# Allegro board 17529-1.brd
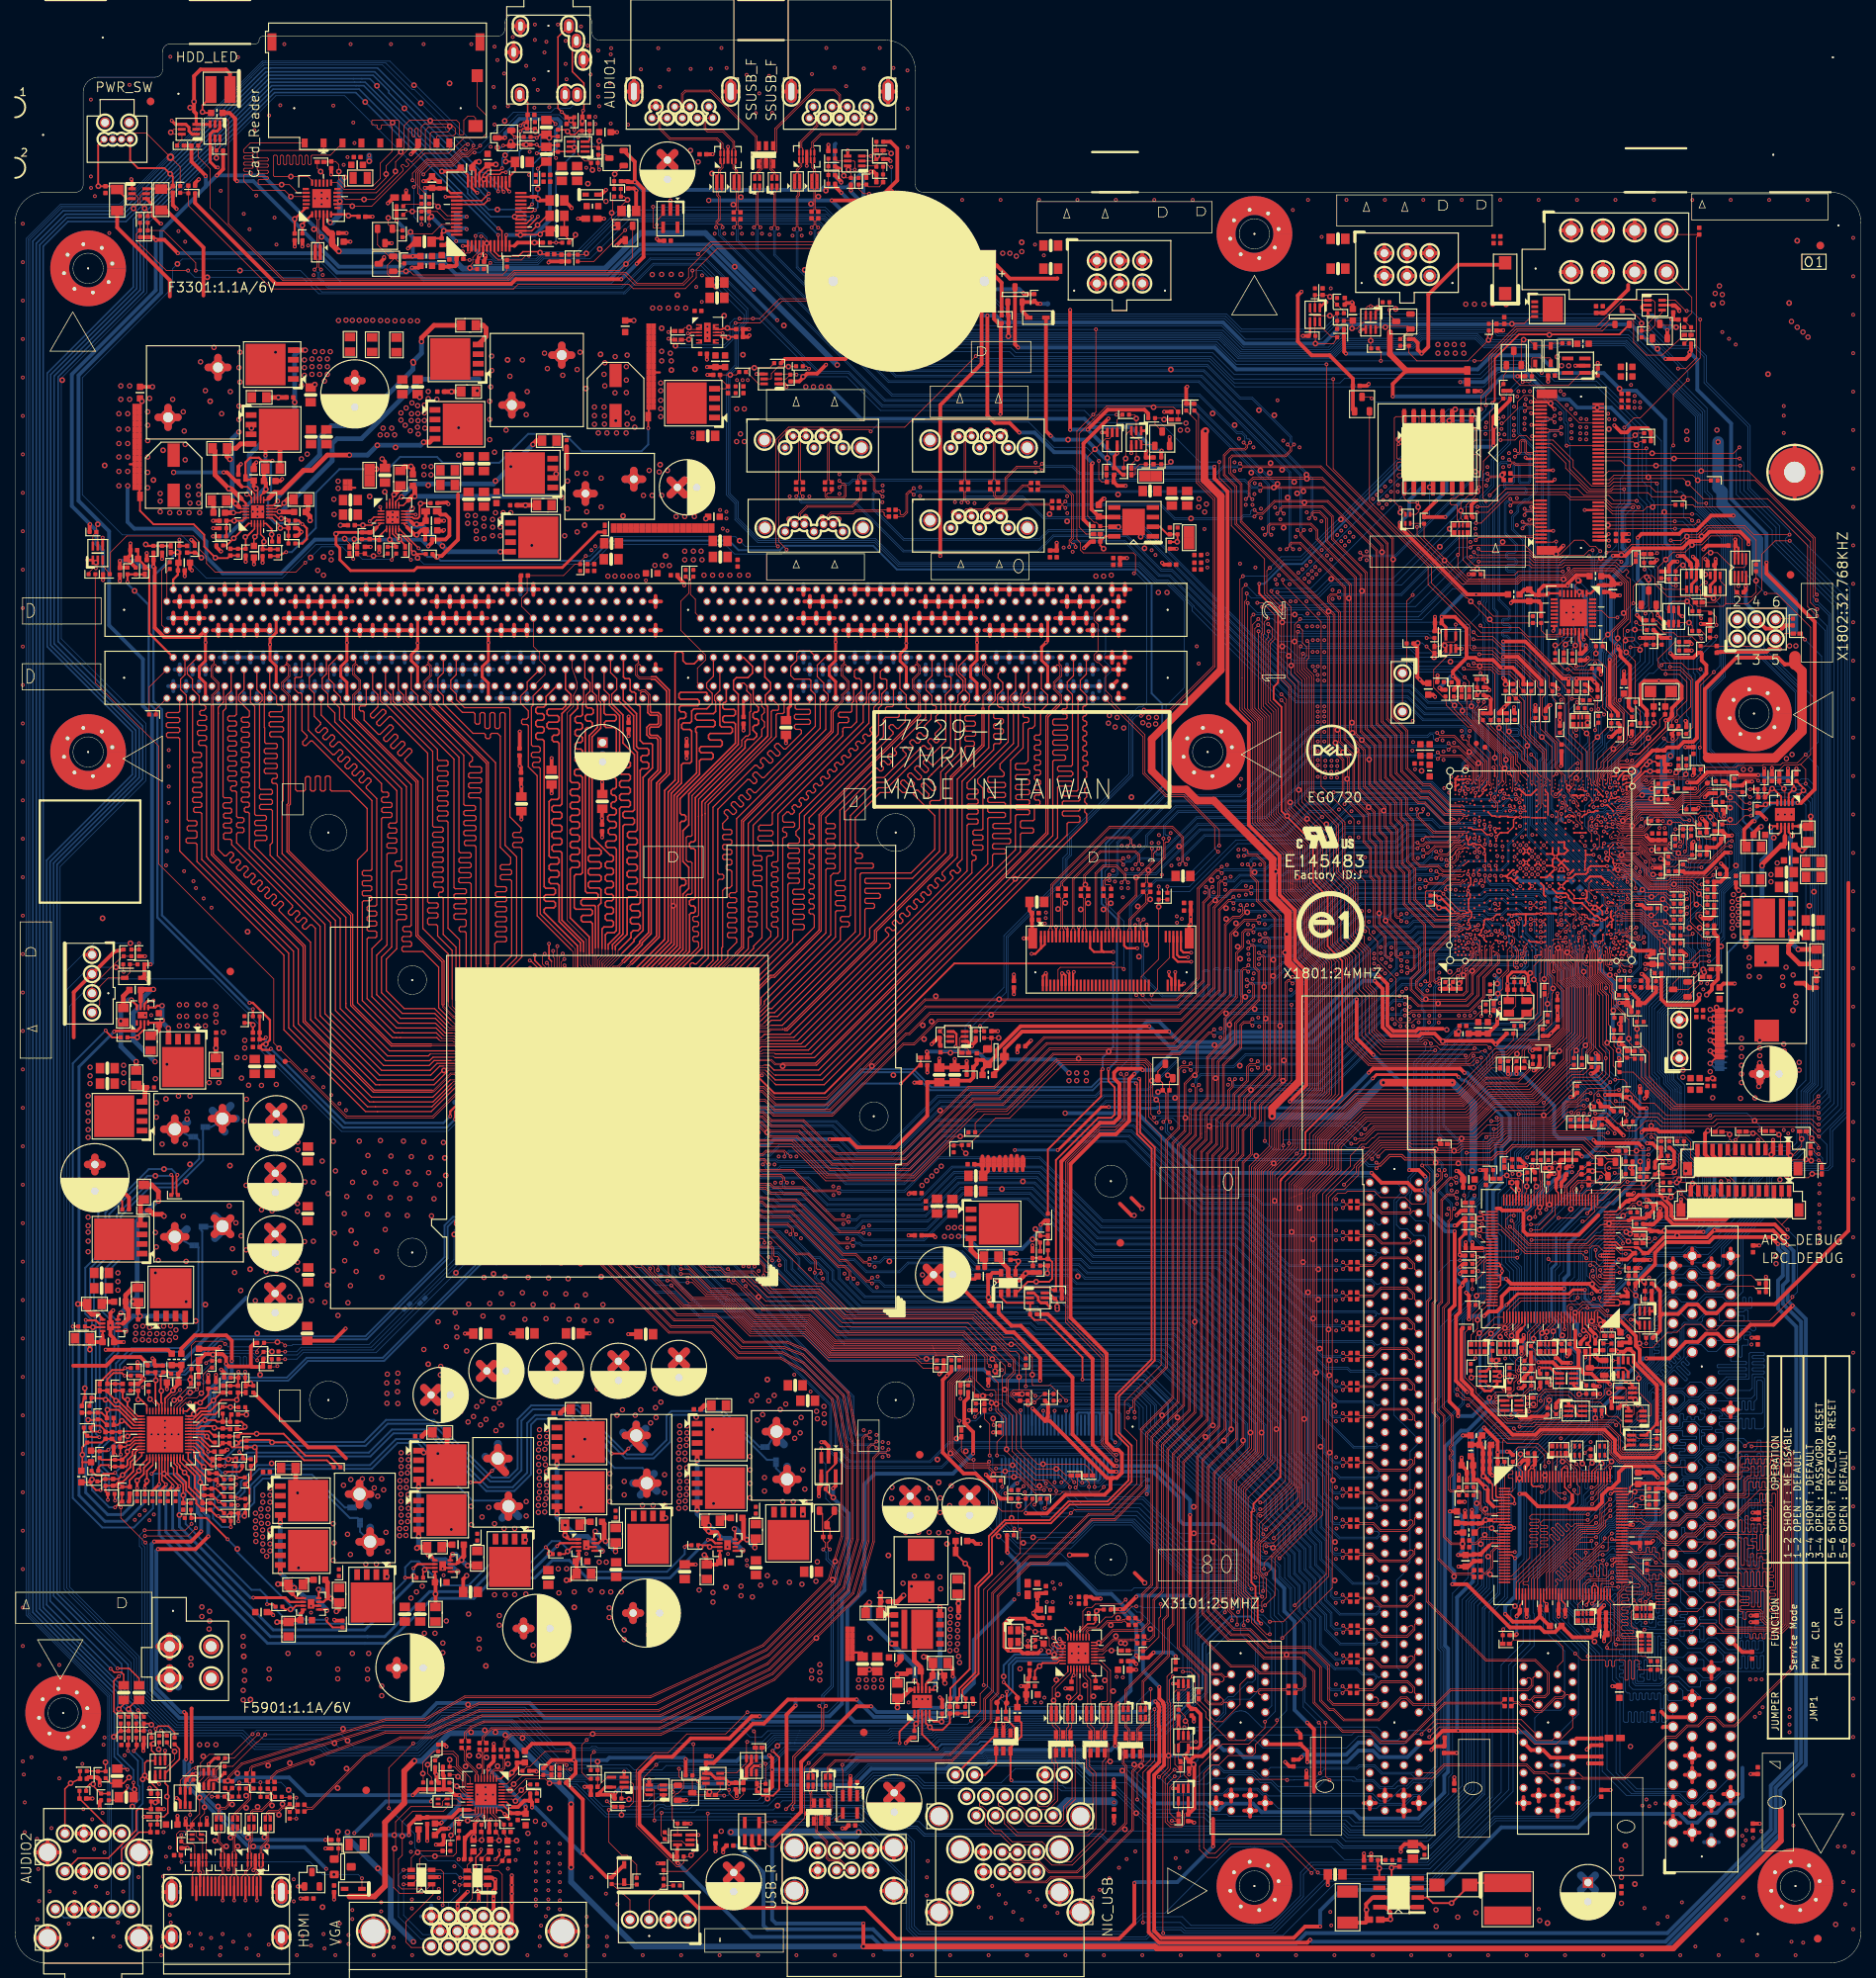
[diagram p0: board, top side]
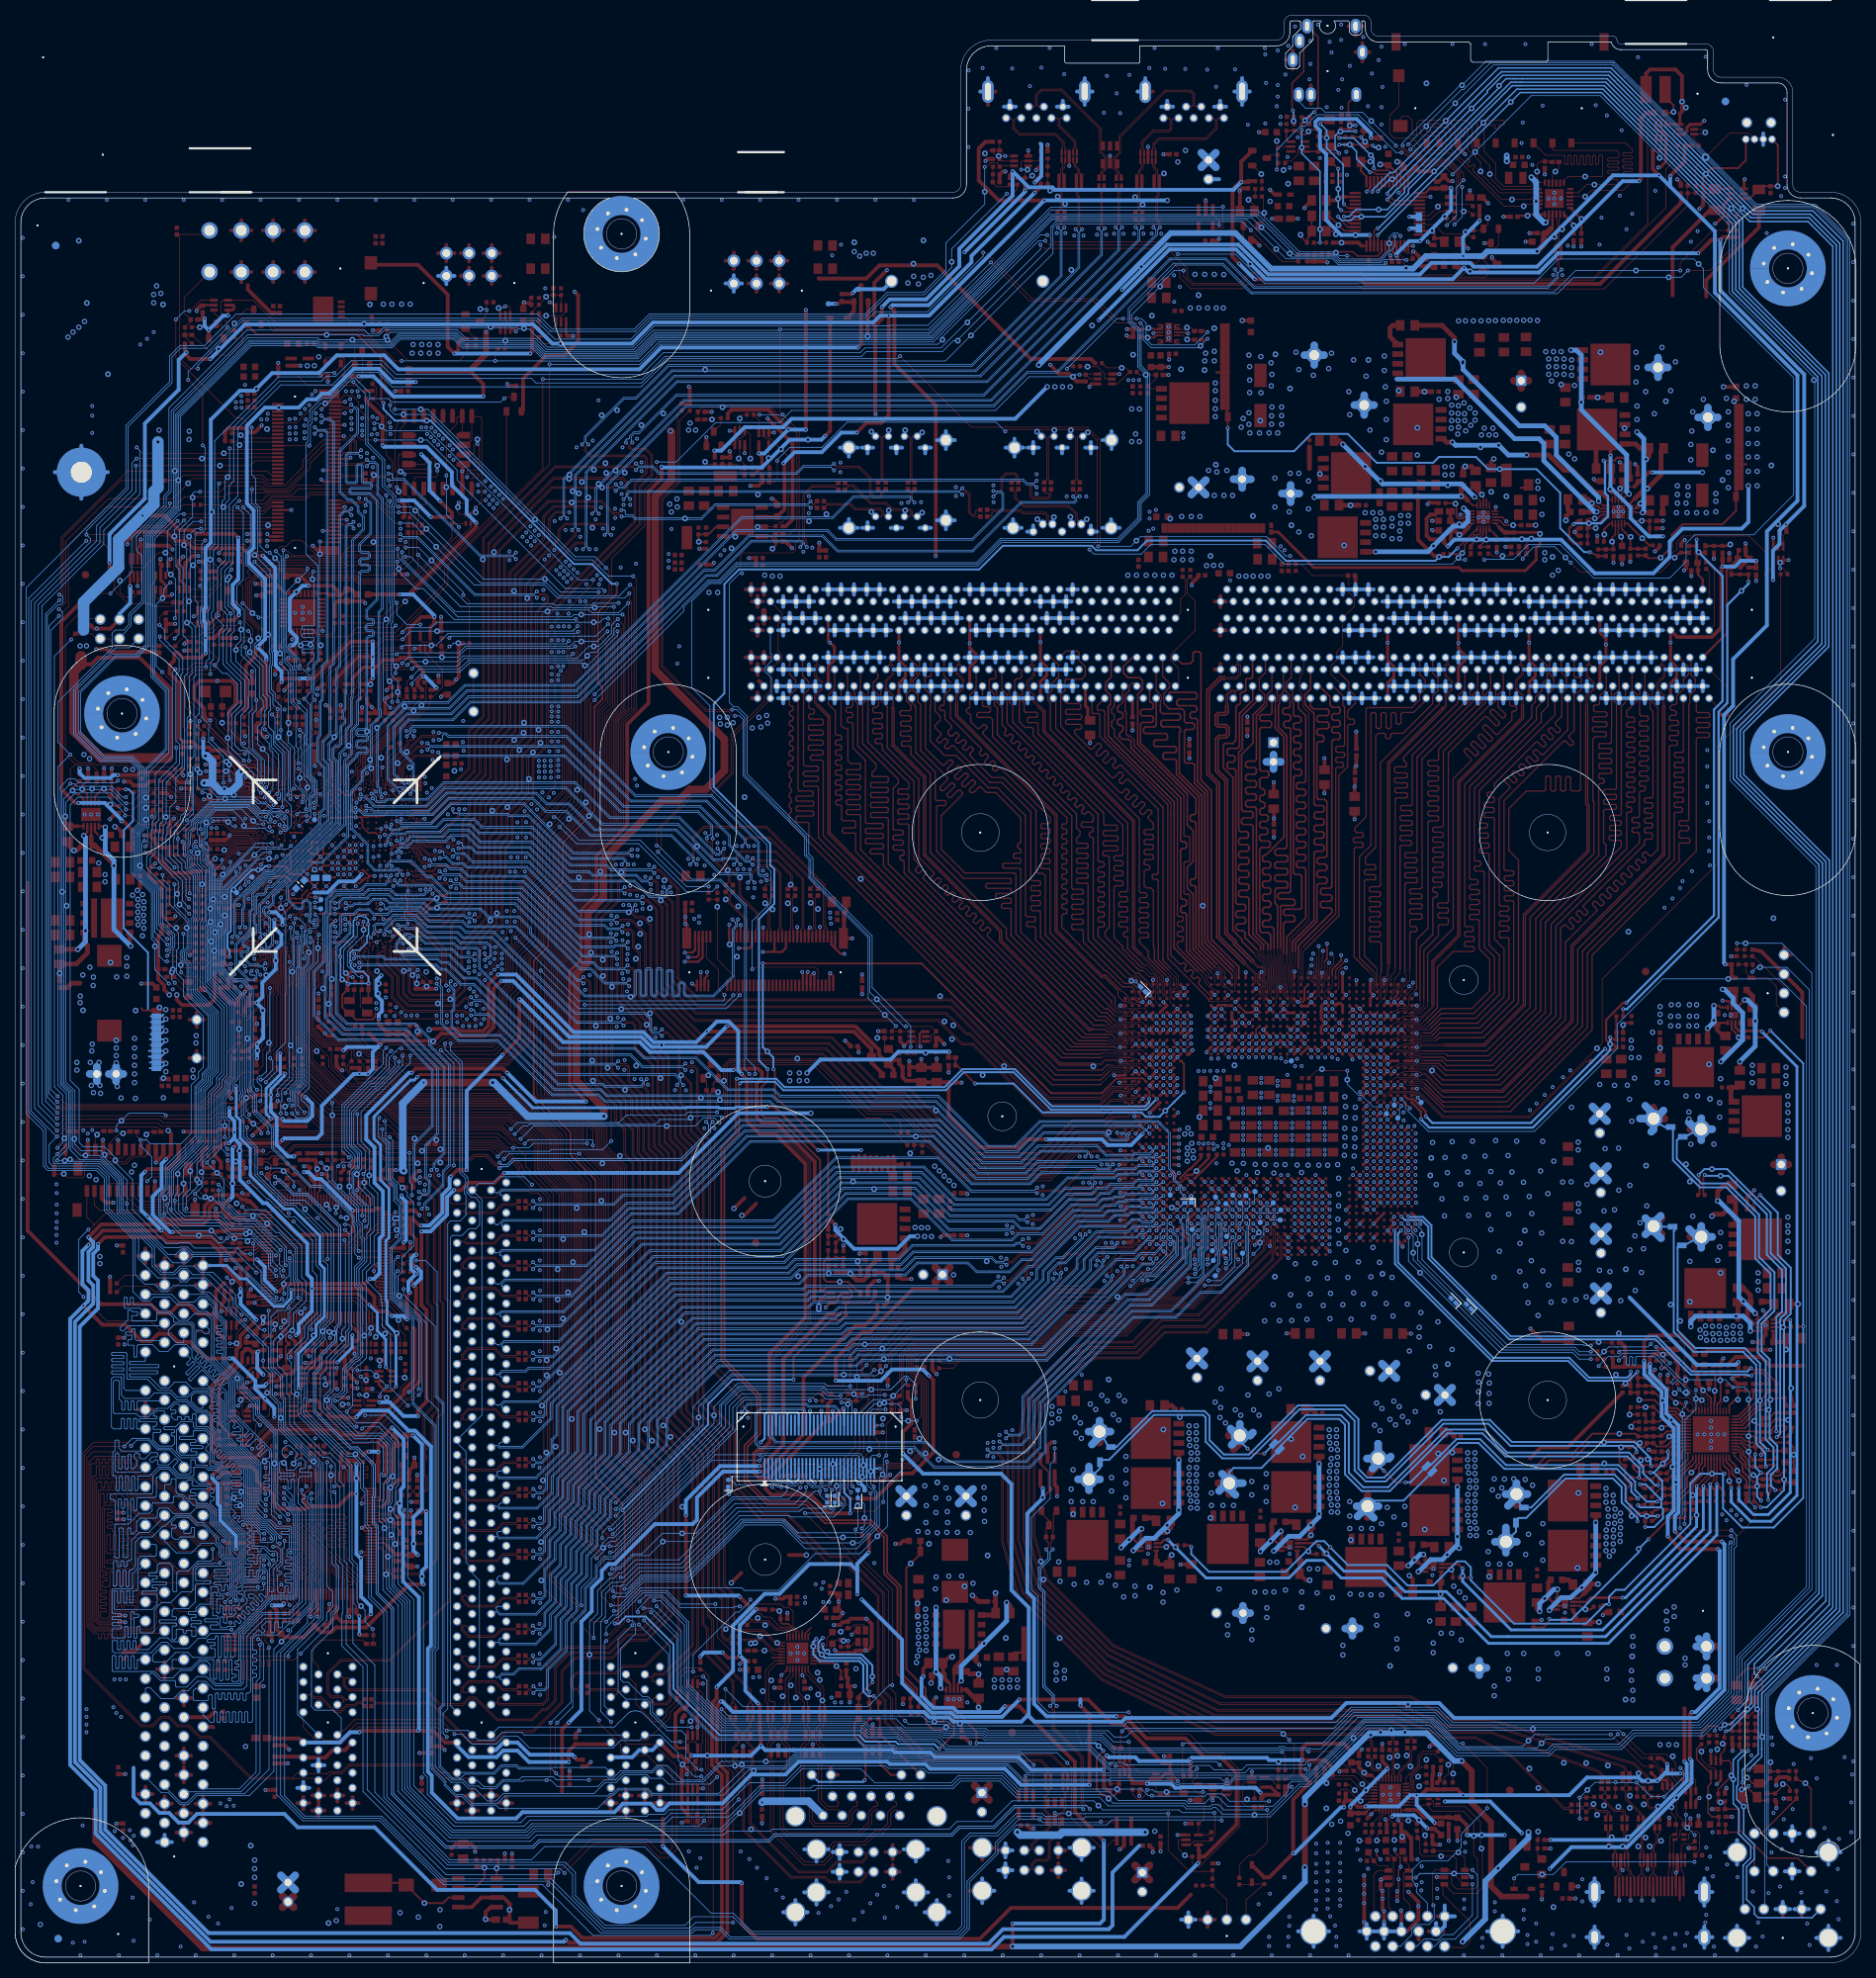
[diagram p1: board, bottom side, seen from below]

Outline 244 x 257.4 mm; copper layers: TOP, L2VCC, L3, BOTTOM. Coordinates in mm from the lower left corner of the outline.
Outline path: 0,230 0,4 arc(1.17,1.17) 4,0 240,0 arc(242.83,1.17) 244,4 244,230 arc(242.83,232.83) 240,234 120,234 arc(119.29,234.29) 119,235 119,250.1 arc(117.83,252.93) 115,254.1 77.25,254.1 arc(76.54,254.39) 76.25,255.1 76.25,256.4 arc(75.96,257.11) 75.25,257.4 65.75,257.4 arc(65.04,257.11) 64.75,256.4 64.75,255.6 arc(64.46,254.89) 63.75,254.6 32.75,254.6 arc(32.4,254.45) 32.25,254.1 arc(32.1,253.75) 31.75,253.6 20.5,253.6 arc(19.79,253.31) 19.5,252.6 19.5,250.2 arc(19.21,249.49) 18.5,249.2 11,249.2 arc(9.59,248.61) 9,247.2 9,235 arc(8.71,234.29) 8,234 4,234 arc(1.17,232.83) 0,230 ; 4.35,33.02 arc(6.35,35.02) 8.35,33.02 arc(6.35,31.02) 4.35,33.02 ; 7.65,223.94 arc(9.65,225.94) 11.65,223.94 arc(9.65,221.94) 7.65,223.94 ; 7.65,160.02 arc(9.65,162.02) 11.65,160.02 arc(9.65,158.02) 7.65,160.02 ; 38.91,74.38 arc(41.41,76.88) 43.91,74.38 arc(41.41,71.88) 38.91,74.38 ; 39.01,149.38 arc(41.41,151.78) 43.81,149.38 arc(41.41,146.98) 39.01,149.38 ; 50.59,129.88 arc(52.49,131.78) 54.39,129.88 arc(52.49,127.98) 50.59,129.88 ; 50.59,93.88 arc(52.49,95.78) 54.39,93.88 arc(52.49,91.98) 50.59,93.88 ; 111.61,111.88 arc(113.51,113.78) 115.41,111.88 arc(113.51,109.98) 111.61,111.88 ; 113.91,149.38 arc(116.41,151.88) 118.91,149.38 arc(116.41,146.88) 113.91,149.38 ; 114.01,74.38 arc(116.41,76.78) 118.81,74.38 arc(116.41,71.98) 114.01,74.38 ; 144.86,105.4 arc(146.96,103.3) 144.86,101.2 arc(142.76,103.3) 144.86,105.4 ; 144.86,55.4 arc(146.96,53.3) 144.86,51.2 arc(142.76,53.3) 144.86,55.4 ; 155.65,160.02 arc(157.65,162.02) 159.65,160.02 arc(157.65,158.02) 155.65,160.02 ; 161.83,228.49 arc(163.83,230.49) 165.83,228.49 arc(163.83,226.49) 161.83,228.49 ; 161.83,10.16 arc(163.83,12.16) 165.83,10.16 arc(163.83,8.16) 161.83,10.16 ; 227.87,165.1 arc(229.87,167.1) 231.87,165.1 arc(229.87,163.1) 227.87,165.1 ; 233.35,10.16 arc(235.35,12.16) 237.35,10.16 arc(235.35,8.16) 233.35,10.16 ; 235.25,198.35 arc(236.6,197) 235.25,195.65 arc(233.9,197) 235.25,198.35

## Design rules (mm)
constraint set DEFAULT: min track width 0.127, pair gap 0.102
net group AUD_AZACPU_SDI: nets AUD_AZACPU_SDI AUD_AZACPU_SDI_R
net group AUDIO_HDA_4_5: nets AUD_LINK_SDO_C AUD_LINK_SDO_R1
net group AUDIO_VREFO_20_10: nets LINE2_VREFO MIC2_VREFO
net group CEC_STRAP: nets GPIO_LAN_RESET_N GPIO_PCI_RESET_N
net group DDI_VGA_DATA_CPU_N2: nets DDI_VGA_DATA_C_N2 DDI_VGA_DATA_CPU_N2
net group DDI_VGA_DATA_CPU_N3: nets DDI_VGA_DATA_C_N3 DDI_VGA_DATA_CPU_N3
net group DDI_VGA_DATA_CPU_P2: nets DDI_VGA_DATA_C_P2 DDI_VGA_DATA_CPU_P2
net group DDI_VGA_DATA_CPU_P3: nets DDI_VGA_DATA_C_P3 DDI_VGA_DATA_CPU_P3
net group DDR_MISC: nets M_A_ALERT# M_B_ALERT#
net group DISPLAY_DDC: nets HDMI_CLK_CPU HDMI_DATA_CPU
net group DP_AUX_CON_N: nets DP_AUX_CON_N DP_AUX_CPU_N
net group DP_AUX_CON_P: nets DP_AUX_CON_P DP_AUX_CPU_P
net group HDMI_DATA_CMC_N0: nets HDMI_DATA_CMC_N0 HDMI_DATA_CPU_N0
net group HDMI_DATA_CMC_N1: nets HDMI_DATA_CMC_N1 HDMI_DATA_CPU_N1
net group HDMI_DATA_CMC_N2: nets HDMI_DATA_CMC_N2 HDMI_DATA_CPU_N2
net group HDMI_DATA_CMC_N3: nets HDMI_DATA_CMC_N3 HDMI_DATA_CPU_N3
net group HDMI_DATA_CMC_P0: nets HDMI_DATA_CMC_P0 HDMI_DATA_CPU_P0
net group HDMI_DATA_CMC_P1: nets HDMI_DATA_CMC_P1 HDMI_DATA_CPU_P1
net group HDMI_DATA_CMC_P2: nets HDMI_DATA_CMC_P2 HDMI_DATA_CPU_P2
net group HDMI_DATA_CMC_P3: nets HDMI_DATA_CMC_P3 HDMI_DATA_CPU_P3
net group LAN_MDI0_DN: nets LAN_MDI0_DN LAN_MDI0_DN_C
net group LAN_MDI0_DP: nets LAN_MDI0_DP LAN_MDI0_DP_C
net group LAN_MDI1_DN: nets LAN_MDI1_DN LAN_MDI1_DN_C
net group LAN_MDI1_DP: nets LAN_MDI1_DP LAN_MDI1_DP_C
net group LAN_MDI2_DN: nets LAN_MDI2_DN LAN_MDI2_DN_C
net group LAN_MDI2_DP: nets LAN_MDI2_DP LAN_MDI2_DP_C
net group LAN_MDI3_DN: nets LAN_MDI3_DN LAN_MDI3_DN_C
net group LAN_MDI3_DP: nets LAN_MDI3_DP LAN_MDI3_DP_C
net group LED_4_5: nets SIO_GREEN SIO_YELLOW
net group PCH_LPSS_GSP: nets LPSS_GSPI0_MOSI LPSS_GSPI1_MOSI
net group PCI_CLK: nets PCI_CLK1 PCICLK0
net group PCIE_RX_CON_N5: nets PCIE_RX_CON_N5 PCIE_RX_PCH_N5
net group PCIE_RX_CON_N6: nets PCIE_RX_CON_N6 PCIE_RX_PCH_N6
net group PCIE_RX_CON_P5: nets PCIE_RX_CON_P5 PCIE_RX_PCH_P5
net group PCIE_RX_CON_P6: nets PCIE_RX_CON_P6 PCIE_RX_PCH_P6
net group PCIE_TX_CON_N5: nets PCIE_TX_CON_N5 PCIE_TX_PCH_N5
net group PCIE_TX_CON_N6: nets PCIE_TX_CON_N6 PCIE_TX_PCH_N6
net group PCIE_TX_CON_N7: nets PCIE_TX_CON_N7 PCIE_TX_PCH_N7
net group PCIE_TX_CON_N9: nets PCIE_TX_CON_N9 PCIE_TX_PCH_N9
net group PCIE_TX_CON_N21: nets PCIE_TX_CON_N21 PCIE_TX_PCH_N21
net group PCIE_TX_CON_N22: nets PCIE_TX_CON_N22 PCIE_TX_PCH_N22
net group PCIE_TX_CON_N23: nets PCIE_TX_CON_N23 PCIE_TX_PCH_N23
net group PCIE_TX_CON_N24: nets PCIE_TX_CON_N24 PCIE_TX_PCH_N24
net group PCIE_TX_CON_P5: nets PCIE_TX_CON_P5 PCIE_TX_PCH_P5
net group PCIE_TX_CON_P6: nets PCIE_TX_CON_P6 PCIE_TX_PCH_P6
net group PCIE_TX_CON_P7: nets PCIE_TX_CON_P7 PCIE_TX_PCH_P7
net group PCIE_TX_CON_P9: nets PCIE_TX_CON_P9 PCIE_TX_PCH_P9
net group PCIE_TX_CON_P21: nets PCIE_TX_CON_P21 PCIE_TX_PCH_P21
net group PCIE_TX_CON_P22: nets PCIE_TX_CON_P22 PCIE_TX_PCH_P22
net group PCIE_TX_CON_P23: nets PCIE_TX_CON_P23 PCIE_TX_PCH_P23
net group PCIE_TX_CON_P24: nets PCIE_TX_CON_P24 PCIE_TX_PCH_P24
net group PEG_TX_CON_N0: nets PEG_TX_CON_N0 PEG_TX_CPU_N0
net group PEG_TX_CON_N1: nets PEG_TX_CON_N1 PEG_TX_CPU_N1
net group PEG_TX_CON_N2: nets PEG_TX_CON_N2 PEG_TX_CPU_N2
net group PEG_TX_CON_N3: nets PEG_TX_CON_N3 PEG_TX_CPU_N3
net group PEG_TX_CON_N4: nets PEG_TX_CON_N4 PEG_TX_CPU_N4
net group PEG_TX_CON_N5: nets PEG_TX_CON_N5 PEG_TX_CPU_N5
net group PEG_TX_CON_N6: nets PEG_TX_CON_N6 PEG_TX_CPU_N6
net group PEG_TX_CON_N7: nets PEG_TX_CON_N7 PEG_TX_CPU_N7
net group PEG_TX_CON_N8: nets PEG_TX_CON_N8 PEG_TX_CPU_N8
net group PEG_TX_CON_N9: nets PEG_TX_CON_N9 PEG_TX_CPU_N9
net group PEG_TX_CON_N10: nets PEG_TX_CON_N10 PEG_TX_CPU_N10
net group PEG_TX_CON_N11: nets PEG_TX_CON_N11 PEG_TX_CPU_N11
net group PEG_TX_CON_N13: nets PEG_TX_CON_N13 PEG_TX_CPU_N13
net group PEG_TX_CON_N14: nets PEG_TX_CON_N14 PEG_TX_CPU_N14
net group PEG_TX_CON_N15: nets PEG_TX_CON_N15 PEG_TX_CPU_N15
net group PEG_TX_CON_P0: nets PEG_TX_CON_P0 PEG_TX_CPU_P0
net group PEG_TX_CON_P1: nets PEG_TX_CON_P1 PEG_TX_CPU_P1
net group PEG_TX_CON_P2: nets PEG_TX_CON_P2 PEG_TX_CPU_P2
net group PEG_TX_CON_P3: nets PEG_TX_CON_P3 PEG_TX_CPU_P3
net group PEG_TX_CON_P4: nets PEG_TX_CON_P4 PEG_TX_CPU_P4
net group PEG_TX_CON_P5: nets PEG_TX_CON_P5 PEG_TX_CPU_P5
net group PEG_TX_CON_P6: nets PEG_TX_CON_P6 PEG_TX_CPU_P6
net group PEG_TX_CON_P7: nets PEG_TX_CON_P7 PEG_TX_CPU_P7
net group PEG_TX_CON_P8: nets PEG_TX_CON_P8 PEG_TX_CPU_P8
net group PEG_TX_CON_P9: nets PEG_TX_CON_P9 PEG_TX_CPU_P9
net group PEG_TX_CON_P10: nets PEG_TX_CON_P10 PEG_TX_CPU_P10
net group PEG_TX_CON_P11: nets PEG_TX_CON_P11 PEG_TX_CPU_P11
net group PEG_TX_CON_P13: nets PEG_TX_CON_P13 PEG_TX_CPU_P13
net group PEG_TX_CON_P14: nets PEG_TX_CON_P14 PEG_TX_CPU_P14
net group PEG_TX_CON_P15: nets PEG_TX_CON_P15 PEG_TX_CPU_P15
net group PWM_12_12: nets DLDO_CAP LDO5V
net group SATA_RX_CON_N0: nets SATA_RX_CON_N0 SATA_RX_PCH_N0
net group SATA_RX_CON_N1: nets SATA_RX_CON_N1 SATA_RX_PCH_N1
net group SATA_RX_CON_N2: nets SATA_RX_CON_N2 SATA_RX_PCH_N2
net group SATA_RX_CON_N3: nets SATA_RX_CON_N3 SATA_RX_PCH_N3
net group SATA_RX_CON_P0: nets SATA_RX_CON_P0 SATA_RX_PCH_P0
net group SATA_RX_CON_P1: nets SATA_RX_CON_P1 SATA_RX_PCH_P1
net group SATA_RX_CON_P2: nets SATA_RX_CON_P2 SATA_RX_PCH_P2
net group SATA_RX_CON_P3: nets SATA_RX_CON_P3 SATA_RX_PCH_P3
net group SATA_TX_CON_N0: nets SATA_TX_CON_N0 SATA_TX_PCH_N0
net group SATA_TX_CON_N1: nets SATA_TX_CON_N1 SATA_TX_PCH_N1
net group SATA_TX_CON_N2: nets SATA_TX_CON_N2 SATA_TX_PCH_N2
net group SATA_TX_CON_N3: nets SATA_TX_CON_N3 SATA_TX_PCH_N3
net group SATA_TX_CON_P0: nets SATA_TX_CON_P0 SATA_TX_PCH_P0
net group SATA_TX_CON_P1: nets SATA_TX_CON_P1 SATA_TX_PCH_P1
net group SATA_TX_CON_P2: nets SATA_TX_CON_P2 SATA_TX_PCH_P2
net group SATA_TX_CON_P3: nets SATA_TX_CON_P3 SATA_TX_PCH_P3
net group SD_CLK_BD: nets SD_CLK_BD U1.15
net group SIO_SCH5553: nets A20GATE PS_ON_N
net group SPI_CLK_ROM1: nets SPI_CLK_PCH SPI_CLK_ROM1
net group SPI_CS_PCH_N2: nets SPI_CS_PCH_N2 TPM_CS
net group SPI_HOLD_ROM1: nets SPI_HOLD_PCH SPI_HOLD_ROM1
net group SPI_SI_ROM1: nets SPI_SI_PCH SPI_SI_ROM1
net group SPI_SO_ROM1: nets SPI_SO_PCH SPI_SO_ROM1
net group SPI_WP_ROM1: nets SPI_WP_PCH SPI_WP_ROM1
net group TPM: nets TPM_PIRQ TPM_RST_R
net group USB30_TX_CMC_N1: nets USB30_TX_CMC_N1 USB30_TX_PCH_N1
net group USB30_TX_CMC_N2: nets USB30_TX_CMC_N2 USB30_TX_PCH_N2
net group USB30_TX_CMC_P1: nets USB30_TX_CMC_P1 USB30_TX_PCH_P1
net group USB30_TX_CMC_P2: nets USB30_TX_CMC_P2 USB30_TX_PCH_P2
net group USB_CON_PN1: nets USB_CON_PN1 USB_PCH_PN1
net group USB_CON_PN2: nets USB_CON_PN2 USB_PCH_PN2
net group USB_CON_PN5: nets USB_CON_PN5 USB_PCH_PN5
net group USB_CON_PN6: nets USB_CON_PN6 USB_PCH_PN6
net group USB_CON_PN7: nets USB_CON_PN7 USB_PCH_PN7
net group USB_CON_PN8: nets USB_CON_PN8 USB_PCH_PN8
net group USB_CON_PN9: nets USB_CON_PN9 USB_PCH_PN9
net group USB_CON_PP1: nets USB_CON_PP1 USB_PCH_PP1
net group USB_CON_PP2: nets USB_CON_PP2 USB_PCH_PP2
net group USB_CON_PP5: nets USB_CON_PP5 USB_PCH_PP5
net group USB_CON_PP6: nets USB_CON_PP6 USB_PCH_PP6
net group USB_CON_PP7: nets USB_CON_PP7 USB_PCH_PP7
net group USB_CON_PP8: nets USB_CON_PP8 USB_PCH_PP8
net group USB_CON_PP9: nets USB_CON_PP9 USB_PCH_PP9
net group AUDIO_IO1_8_10: nets AUD_BEEP AUD_LINE1_L AUD_LINE1_R AUD_LINE2_L AUD_LINE2_R AUD_MIC1_L AUD_MIC1_R AUD_MIC2_L AUD_MIC2_L_C AUD_MIC2_R AUDOUT_L AUDOUT_LL AUDOUT_R AUDOUT_RR HP_OUT_L HP_OUT_R LINE1_LL LINE1_LL_C LINE1_RR LINE1_RR_C LINEIN_L LINEIN_R MIC1_LL MIC1_LL_C MIC1_RR MIC1_RR_C MIC1_VREFO_LL MIC1_VREFO_RR PF_MIC2_LL RP_AUDOUT_L RP_AUDOUT_R RP_LINE1_L RP_LINE1_R RP_MIC1_L RP_MIC1_R
net group AUDIO_IO2_8_8: nets FP_MIC2_L FP_OUT_L FP_OUT_LL FP_OUT_R FP_OUT_RR
net group AUDIO_JD: nets FRONT_JD LINE1_JD LINE1_JD/LINE2_JD LINE2_JD MIC1_JD MIC1_JD/FRONT_JD
net group AUDIO_OTHER: nets AUD_BEEP_R
net group CEC_PCH_SYSPWROK: nets PCH_SYSPWROK_EXTD1 PCH_SYSPWROK_EXTD2 PCH_SYSPWROK_EXTD3
net group CEC_PLTRST_N: nets PLTRST#_PCH PLTRST#_SIO PLTRST_BUF_LAN_N PLTRST_BUF_PCI_N PLTRST_PCON_N
net group CEC_PS_ON: nets CEC_PS_ON_N CEC_PS_ON_N_EXTD1 CEC_PS_ON_N_EXTD2 PCH_PS_ON_N PCH_PS_ON_N_EXTD1
net group CNVI_BUS: nets CNV_DET_G GPP_J0_CNV_BLANKING GPP_J8_CNV_RXD GPP_J9_CNV_TXD PCM_CLK PCM_IN PCM_OUT PCM_OUT_C PCM_SYNC PCM_SYNC_C
net group COM: nets SP_CTS_N SP_DCD_N SP_DSR_N SP_DTR_N SP_RI_N SP_RTS_N SP_RXD_N SP_RXD_N_CON SP_TXD_N SP_TXD_N_1 SP_TXD_SIO SP_TXD_SIO_CON
net group CPU_CFG_RCOMP: nets TPEV_CFG_RCOMP
net group DDI_HDP: nets DP_HPD_CPU HDMI_DET_CPU VGA1_DETECT
net group DDR4_A_ADDR_CMD-MWS: nets M_A_A0 M_A_A1 M_A_A2 M_A_A3 M_A_A4 M_A_A5 M_A_A6 M_A_A7 M_A_A8 M_A_A9 M_A_A10 M_A_A11 M_A_A12 M_A_A13 M_A_A14 M_A_A15 M_A_A16 M_A_ACT# M_A_BG0 M_A_BG1 M_A_BS0 M_A_BS1 M_A_PARITY
net group DDR4_B_ADDR_CMD-MWS: nets M_B_A0 M_B_A1 M_B_A2 M_B_A3 M_B_A4 M_B_A5 M_B_A6 M_B_A7 M_B_A8 M_B_A9 M_B_A10 M_B_A11 M_B_A12 M_B_A13 M_B_A14 M_B_A15 M_B_A16 M_B_ACT# M_B_BG0 M_B_BG1 M_B_BS0 M_B_BS1 M_B_PARITY
net group DDR4_B_CTRL: nets M_B_CKE0 M_B_CKE1 M_B_CS#0 M_B_CS#1 M_B_ODT0 M_B_ODT1
net group DDR4_B_DATA-MWS: nets M_B_DQ0 M_B_DQ1 M_B_DQ2 M_B_DQ3 M_B_DQ4 M_B_DQ5 M_B_DQ6 M_B_DQ7 M_B_DQ8 M_B_DQ9 M_B_DQ10 M_B_DQ11 M_B_DQ12 M_B_DQ13 M_B_DQ14 M_B_DQ15 M_B_DQ16 M_B_DQ17 M_B_DQ18 M_B_DQ19 M_B_DQ20 M_B_DQ21 M_B_DQ22 M_B_DQ23 M_B_DQ24 M_B_DQ25 M_B_DQ26 M_B_DQ27 M_B_DQ28 M_B_DQ29 M_B_DQ30 M_B_DQ31 M_B_DQ32 M_B_DQ33 M_B_DQ34 M_B_DQ35 M_B_DQ36 M_B_DQ37 M_B_DQ38 M_B_DQ39 M_B_DQ40 M_B_DQ41 M_B_DQ42 M_B_DQ43 M_B_DQ44 M_B_DQ45 M_B_DQ46 M_B_DQ47 M_B_DQ48 M_B_DQ49 M_B_DQ50 M_B_DQ51 M_B_DQ52 M_B_DQ53 M_B_DQ54 M_B_DQ55 M_B_DQ56 M_B_DQ57 M_B_DQ58 M_B_DQ59 M_B_DQ60 M_B_DQ61 M_B_DQ62 M_B_DQ63
net group DDR_VREF_CA: nets DIMM_CA_CPU_VREF_RC DIMM_CA_VREF_A DIMM_CA_VREF_A_L DIMM_CA_VREF_B DIMM_CA_VREF_B_L DIMM_DQ_CPU_VREF_B_RC M_VREF_DQ_DIM1 V_SM_VREF_CNT
net group DEEPSLEEP_CON_4_5: nets FP_RST_N_CN PCH_DPWROK PCH_SLP_A_N PWRBTN_N_CN SIO_PS_ON_N SLP_A_N_CN SLP_S0_N SLP_S4_N_SFR SLP_S4_N_SFR_1 SLP_S4_N_SFR_2 SLP_S4_N_SFR_G SLP_SUSB SUS_WARNB VTT_EN
net group DSW_4_8: nets SUS_ACK_EN_N SUS_PWR_ACK SUS_WARNB_R
net group FAN_CPU: nets CPU_FAN_CTRL_CONN CPU_FAN_CTRL_SIO CPU_FAN_TACH_1 CPU_FAN_TACH_SIO
net group FAN_SYS1: nets SYS_FAN_CTRL_CONN SYS_FAN_CTRL_SIO SYS_FAN_TACH_1 SYS_FAN_TACH_SIO
net group FDI_COMP: nets FDI_COMP
net group GPIO_4: nets 3P3V_S5_EN ACPRESENT BATLOW_N CNV_BRI_DT CNV_BRI_DT_R CNV_BRI_RSP CNV_BRI_RSP_R CNV_RGI_DT CNV_RGI_DT_R CNV_RGI_RSP CNV_RGI_RSP_R CNV_WT_RCOMP DDR_VTT_CNTL_CPU DDR_VTT_CNTL_GATE DDR_VTT_CNTL_R DDSP_B_TX_N0 DIMM1_EVENT_N DIMM2_EVENT_N EAPD FORM_FAC_ID_0 FORM_FAC_ID_1 FORM_FAC_ID_2 FORM_FAC_ID_3 FP_CBL_DET_PD GPP_A7 GPP_A8 GPP_H_12 GPP_H_15 GPP_K5 H_SKTOCC_CPU H_SKTOCC_N HDMI1_DETECT HDMI_DET_CON LANCLK_REQ_U_N LPC_PME_N ME_CNTL ME_CNTL_1 ME_CNTL_2 MUTE MUTE_AUDOUT_LL MUTE_AUDOUT_RR MUTE_FP_OUT_LL MUTE_FP_OUTR_RR PC_SPKR_DET_PD PCH_HEATSINK_DET PM_DOWN_CPU PM_DOWN_PCH PM_SYNC_CPU PM_SYNC_PCH PW_CLEAR Q82_B Q83_B Q84_B Q84_E Q84_E2 Q85_B S0_5V_EN S4_VPP_OR SB3V_EN SLP_S4_VPP_N SM_PGCNTL SMBALERT_N SML0ALERT# SSD_PEDET SSD_PEWAKE_N TMIN_SHIFT TMIN_SHIFT_PCH TP_RSVD3_BC1 UART_BT_WAKE_N USB2_ID USB2_VBUSSENSE V5_ALW_MON V5_ALW_MON_1 V5_ALW_MON_2 VDDQ_EN VGA_CABLE_DET_N VPP_EN VPP_EN_DDR4 W_DISABLE#1 W_DISABLE#2 WAKE_M2_SSD_N WLAN_PEDET WLAN_USB_DET
net group HDA_BITCLK_CODEC: nets HDA_BITCLK_CODEC
net group HDA_RST#_CODEC: nets HDA_RST#_CODEC
net group HDA_SDOUT_CODEC: nets HDA_SDOUT_CODEC
net group HDD_LED_CTL: nets DAS/DSS# DAS/DSS#_NMOS PCH_SATA_LED_N PCH_SATA_LED_NMOS
net group KBMS: nets KBRST_N KCLK KDAT MCLK MDAT
net group LAN_8111H: nets RTL_ISOLATE_N
net group LAN_LED: nets LAN_LEDACT_R# LINK_ACTIVITY_N SPEED_100*_CON SPEED_100_N SPEED_1000*_CON SPEED_1000_N
net group LAN_WG1217LM: nets LANWAKE_R_N
net group LPC: nets LPC_AD_PCH_P0 LPC_AD_PCH_P1 LPC_AD_PCH_P2 LPC_AD_PCH_P3 LPC_FRAME#_PCH LPC_FRAME#_PCH_R LPC_SERIRQ_PCH
net group LPC_CLK: nets LPC_CLK_14M_DEBUG LPC_CLK_14M_EC LPC_CLK_33M_EC LPC_CLK_PCH_P0 LPC_CLK_PCH_P1
net group MT_ONLY: nets 12V_DETECT 12V_DETECT_1 12V_DETECT_2 12V_DETECT_DELAY +12V_PG SLP_S3_N_R SLP_S3_N_R_1
net group OSCILLATION: nets CLKIN_XTAL LAN_XTALI LAN_XTALO LAN_XTALO_C PCH_RTCRST_DOWN PULSAR_38D4M_REFCLK XCLK_RBIAS
net group PCH_CIRTIAL: nets PROC_TRIGIN_CPU PROC_TRIGIN_PCH PROC_TRIGOUT_CPU PROC_TRIGOUT_PCH VR_READY VR_READY_A VR_READY_B VR_READY_IMVP XDP_VR_READY
net group PCH_CIRTIAL2: nets FP_RST_N PCH_SIO_DPWROK PCH_SYSPWROK PCH_WAKE_N PWR_BTNJ_C PWRBTN_N RSMRST_SIO_N RSMRST_SIO_N_1 THERMTRIP#_CPU THERMTRIP#_PCH
net group PCI: nets ACK64_N1 EXT_ARB IDSEL_1 PCIAUX_GATE PCICLK_SEL PGNT1# PINTA_N PINTB_N PINTC_N PINTD_N PME_N PME_N_1 PREQ1# REQ64B_N1 RREF RST_SEL TEST_EN TP0 TP1
net group PCIE_TX_CON_N8: nets PCIE_TX_CON_N8
net group PCIE_TX_CON_P8: nets PCIE_TX_CON_P8
net group PCM_WIFI: nets PCM_CLK_PCH PCM_IN_PCH PCM_OUT_PCH PCM_SYNC_PCH
net group PECI: nets PCH_PECI PECI_EC PECI_READY SIO_PECI_REQ_N
net group PECI_TF18: nets PECI_CPU
net group PEG_CLKREQ_PCH: nets PEG_CLKREQ1_PCH# PEG_CLKREQ2_PCH# PEG_CLKREQ3_PCH# PEG_CLKREQ8_PCH# PEG_CLKREQ9_PCH# PEG_CLKREQ10_PCH# PEG_CLKREQ11_PCH#
net group PEG_RCOMP: nets PCIE_RCOMP_N PCIE_RCOMP_P PEG_RCOMP_CPU
net group POWER_10_5: nets HDD_LED_PWR1 PWR_LED_G PWR_LED_Y VCCPLL_OC_R
net group POWER_12_5: nets U1.1 U1.6 U1.24
net group POWER_20_5: nets 1.8VA 1.8VAAUX 1.8VD 1.8VDAUX ALDO_CAP CBN CBP CPVEE EDP_AVC33 EDP_DAC33 LDO_18V LDO_AUX_18V TPM_VDD_P8
net group POWER_35_5: nets 3P0V_BAT_VREG VBAT1 VBAT1_L VBAT1_R VBAT2
net group POWER_40_5: nets EDP_AVC12
net group POWER_40_5_V: nets 5V_DDC_HDMI
net group POWER_80_5: nets 1V_VCCDSW
net group PROCHOT: nets PROCHOT#_CPU PROCHOT#_CPU_R PROCHOT#_EC PROCHOT#_IMVP
net group PWM_8_5: nets DCPRTC
net group PWM_10_10: nets NPC3063_#8 NPC3063_COMP NPC3063_SWC NPC3063_SWE NPC3063_TCAP SB3V_CT2 SB5V_CT1 VCCIO_SENSE
net group PWM_20_10: nets CAP_1 TRST_N VIN_DET
net group PWM_LED_20: nets SATA_LED_OUT
net group PWR_10_10: nets PWR_1D0V_CS PWR_1D0V_FB PWR_1D0V_PG PWR_1D0V_RF PWR_2D5V_EN PWR_2D5V_FB PWR_3V_CS2 PWR_3V_EN2 PWR_3V_FB2 PWR_3V_FB2_A PWR_5V_CS1 PWR_5V_EN1 PWR_5V_FB1 PWR_5V_FB1_A PWR_DDR4_CS PWR_DDR4_FB PWR_GT_COMP PWR_GT_COMP_A PWR_GT_COMP_R PWR_GT_CSCOMP PWR_GT_CSP1_IC PWR_GT_CSP2_IC PWR_GT_CSREF PWR_GT_CSSUM PWR_GT_DOUT PWR_GT_EN1 PWR_GT_EN2 PWR_GT_FB PWR_GT_ILIM PWR_GT_IOUT PWR_GT_TCP PWR_GT_TSNS PWR_GT_TSNS_R PWR_GT_VSN PWR_GT_VSP PWR_PSYS PWR_RT6575_PG PWR_VCCIO_FB PWR_VCCIO_FB1 PWR_VCCIO_FB2 PWR_VCCIO_FB3 PWR_VCCIO_SS PWR_VCCIO_VCCSA_EN PWR_VCCSA_CS PWR_VCCSA_FB PWR_VCCSA_FB1 PWR_VCCSA_PG PWR_VCCSA_RF PWR_VCORE_COMP PWR_VCORE_COMP_A PWR_VCORE_COMP_R PWR_VCORE_CSCOMP PWR_VCORE_CSP1_IC PWR_VCORE_CSP2_IC PWR_VCORE_CSP3_IC PWR_VCORE_CSP4_IC PWR_VCORE_CSREF PWR_VCORE_CSSUM PWR_VCORE_DOUT PWR_VCORE_DRVON PWR_VCORE_EN1 PWR_VCORE_EN2 PWR_VCORE_EN3 PWR_VCORE_EN4 PWR_VCORE_FB PWR_VCORE_ILIM PWR_VCORE_IOUT PWR_VCORE_SCLK PWR_VCORE_SDIO PWR_VCORE_TCP PWR_VCORE_TSNS PWR_VCORE_TSNS_R PWR_VCORE_VRMP PWR_VCORE_VSN PWR_VCORE_VSP PWR_VDDQ_PG PWR_VDDQ_PG_ISOLATE PWR_VDDQ_S3_EN PWR_VDDQ_S5_EN PWR_VDDQ_TON
net group PWR_15_20: nets PWR_GT_PWM1 PWR_GT_PWM2 PWR_VCORE_PWM1 PWR_VCORE_PWM2 PWR_VCORE_PWM3 PWR_VCORE_PWM4
net group PWR_20_10: nets PWR_GT_VCC1 PWR_GT_VCC2 PWR_RT6575_VIN PWR_VCCIO_VCC PWR_VCCSA_VCC PWR_VCORE_VCC PWR_VCORE_VCC1 PWR_VCORE_VCC2 PWR_VCORE_VCC3 PWR_VCORE_VCC4 PWR_VDDQ_VDDP PWR_VDDQ_VIOP
net group PWR_25_20: nets PWR_1D0V_BOOT PWR_1D0V_BOOT_R PWR_1D0V_LGATE PWR_1D0V_UGATE PWR_1D0V_UGATE_R PWR_3D3V_SN PWR_3V_BOOT2 PWR_3V_BOOT2_R PWR_3V_LGATE2 PWR_3V_UGATE2 PWR_3V_UGATE2R PWR_5V_BOOT1 PWR_5V_BOOT1_R PWR_5V_LGATE1 PWR_5V_SN PWR_5V_UGATE1 PWR_5V_UGATE1R PWR_DDR4_BT PWR_DDR4_BT1 PWR_DDR4_LG PWR_DDR4_UG PWR_GT_BST1 PWR_GT_BST1_R PWR_GT_BST2_R PWR_GT_HG1 PWR_GT_HG1_R PWR_GT_HG2 PWR_GT_HG2_R PWR_GT_LG1 PWR_GT_LG2 PWR_GT_SNB1 PWR_GT_SNB2 PWR_VCCIO_DRV PWR_VCCIO_DRV_R PWR_VCCSA_BOOT PWR_VCCSA_BOOT_R PWR_VCCSA_LG PWR_VCCSA_SNB PWR_VCCSA_UG PWR_VCCSA_UG_R PWR_VCORE_BST1 PWR_VCORE_BST1_R PWR_VCORE_BST2 PWR_VCORE_BST2_R PWR_VCORE_BST3 PWR_VCORE_BST3_R PWR_VCORE_BST4 PWR_VCORE_BST4_R PWR_VCORE_HG1 PWR_VCORE_HG2 PWR_VCORE_HG3 PWR_VCORE_HG4 PWR_VCORE_LG1 PWR_VCORE_LG2 PWR_VCORE_LG3 PWR_VCORE_LG4 PWR_VCORE_SNB2 PWR_VCORE_SNB3 PWR_VCORE_SNB4 PWR_VDDQ_SNB
net group PWR_40_10: nets PWR_5V3D3V_LDO3 PWR_DDR4_VDDQ PWR_DDR4_VTTREF PWR_RT6575_LDO5
net group PWRGD&RST_4_8: nets 5V_DISPLAY_SFR_G 12VBDC_EN 12VBDC_EN_1 12VBDC_EN_2 ALL_SYS_PWRGD EC_PWRGD_3V GPD10 GPIO_PEG_RESET_N GPP_A14 GPP_J1 GPP_K3 H_PWRGD H_PWRGD_R H_RSTOUT_XDP_N H_TRST_N_R I2S1_SFRM IO_SMI_N ITP_PMODE PCH_PWROK PCH_PWROK_EC PCIE_SLOT1_PRSNT_N PCIE_SLOT1_PRSNT_N_R PCIE_SLOT2_PRSNT_N PCIE_SLOT2_PRSNT_N_R PCIE_SLOT4_PRSNT_N PCIE_SLOT4_PRSNT_N_R PCIRST1# PCIRST2# PLTRST_CPU_N PLTRST_LAN_N PLTRST_PCI_N PLTRST_PEG_N PSPWRGD PWRGD_VPP S3_QUK S4_VPP_OR_R SIO_SPKR SLP_S0_N_EXTD1 SLP_S0_N_EXTD2 SLP_S0_PLT_N SLP_S3_N SLP_S3_N_CN SLP_S3_N_EXTD1 SLP_S4_N SLP_S4_N_CN SLP_WLAN_N SM_DRAMRST# V_VCC3P3_EN V_VCC3P3_EN_R VCCST_GD_CPU VCCST_GD_DRIVER VCTRL_VCC_EN VDDQ_EN_CR VPP_EN_CR VR_ENABLE VR_ENABLE_IMVP VTT_EN_CR XDP_PWRGD
net group RGB_4_20: nets BLUE_CRT EDP_5VDDCCL EDP_5VDDCDA EDP_BLUE_P EDP_GREEN_P EDP_HSYNC EDP_HSYNC_C EDP_RED_P EDP_VSYNC EDP_VSYNC_C GREEN_CRT RED_CRT
net group SIO_PWR_SNCE: nets MB_REG_PG MB_REG_PG_1 MB_REG_PG_2 MB_REG_PG_3 MEM_REG_PG MEM_REG_PG_1 MEM_REG_PG_2 PWR2_PRSN_1 PWR2_PRSN_2 PWR2_PRSNT
net group SMBUS: nets DDPC_CTRL_CLK DDPC_CTRL_DATA DDPD_CTRL_CLK DDPD_CTRL_DATA HDMI_CLK_CON HDMI_DATA_CON I2C0_SCL_VGA I2C0_SDA_VGA SIO_SMBCLK1 SIO_SMBCLK2 SIO_SMBDAT1 SIO_SMBDAT2 SMB_CLK_MAIN SMB_CLK_RESUME SMB_DATA_MAIN SMB_DATA_RESUME SML0CLK_PCH SML0DATA_PCH SMLICLK_PCH SMLIDATA_PCH
net group SPEKER_4_6: nets SPKR
net group SPI: nets PIRQA_N
net group SUS_CLOCK: nets SUSCLK SUSCLK_SIO SUSCLK_WIFI
net group TH_SET: nets TH_SET
net group TP_4_5: nets BPM_CPU_N2 BPM_CPU_N3 CATERR#_CPU CPU1_AY3 CPU1_G8 DISP_UTIL_CPU GPD7 M_VREF_DQ_DIM0 SKL_CNL_N TP_CPU1_AB35 TP_CPU1_AB37 TP_CPU1_AB38 TP_CPU1_AC37 TP_CPU1_AJ22 TP_CPU1_D15 TP_CPU1_L8 TP_DIMM1_PIN1 TP_DIMM1_PIN145 TP_DIMM2_PIN1 TP_DIMM2_PIN145 TP_PCH_AH14 TP_PCH_AH15 TP_SLP_LAN_N TP_VCCPHY_SENSE TP_VSS_AL37 TP_VSSPHY_SENSE TPM_PP UART0_RX UART0_TX
net group TRACE_4_5: nets +12V_PG_U29 CNV_DET_S EDP_EXPCLKIN EDP_GPI1 EDP_GPI2 EDP_GPI3 EDP_LDORSTB NGFF_WIFI_PWR_CRL NGFF_WIFI_PWR_EN POL1_SDA POL2_SCL SIO_GREEN_1 SIO_YELLOW_1 SUS_PWR_ACK_5V_DUAL SUS_PWR_ACK_5V_DUAL_L SUS_PWR_ACK_BJT SUS_PWR_ACK_BJT_L SUS_PWR_ACK_R SYS_FAN2_TACH_SIO TS_CRIT#
net group TRACE_10_10: nets AUD_VREF LAN_RSET PWRGD_PS
net group USB2_COMP: nets USB2_COMP
net group USB30_RX_CON_N1: nets USB30_RX_PCH_N1
net group USB30_RX_CON_N2: nets USB30_RX_PCH_N2
net group USB30_RX_CON_P1: nets USB30_RX_PCH_P1
net group USB30_RX_CON_P2: nets USB30_RX_PCH_P2
net group USB_OC: nets USB_OC0_R_N USB_OC1_R_N USB_OC2_R_N USB_OC3_R_N USB_OC4_R_N USB_OC5_R_N USB_OC6_R_N
net group VBAT_RST_4_10: nets PCH_INTRUDER_N PCH_RTCRST_N RTCRST_N_CN
net group VRD_4_10: nets VIDALERT#_CPU VIDALERT#_CPU_R VIDSCK_CPU VIDSCK_CPU_R VIDSOUT_CPU VIDSOUT_CPU_R
net group XDP: nets BPM_CPU_N0 BPM_CPU_N1 H_PRDY_N H_PREQ_N H_TCK H_TDI H_TDO H_TMS H_TRST_N PCH_JTAG_TCK PCH_JTAG_TDI PCH_JTAG_TDO PCH_JTAG_TMS PCH_JTAGX PCH_XDP_PRDY_R_N PCH_XDP_PREQ_R_N SKL_PCUDEBUG_0 SKL_PCUDEBUG_1 SKL_PCUDEBUG_2 SKL_PCUDEBUG_3 SKL_PCUDEBUG_4 SKL_PCUDEBUG_5 SKL_PCUDEBUG_6 SKL_PCUDEBUG_7 SKL_PCUDEBUG_8 SKL_PCUDEBUG_9 SKL_PCUDEBUG_10 SKL_PCUDEBUG_11 SKL_PCUDEBUG_12 SKL_PCUDEBUG_13 SKL_PCUDEBUG_14 SKL_PCUDEBUG_15 XDP_PCUDEBUG_3 XDP_PRS XDP_PWR_DEBUG
net group XIO2001: nets PCH_PME_N

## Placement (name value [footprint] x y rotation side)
APS1  JWT-CON13-3-GP  [A1002WV0-13PS-5E]  228.4 104.95 180 top
ATX2  FOX-CONN4F-1-GP  [HM3502E-P1]  23.16 39.72 270 top
ATX3  LIN-CONN8B-S-GP-U  [AT4203W-D067-08E801B-U]  212 226.2 0 top
AUD1  AUDIO-JK187-GP  [ABA-JAK-028-K03]  10.33 3.3 180 top
BT2501  BAT-20-00950-1A01-A-GP-U  [20-00950-1A01-A-U]  116.34 222.23 0 top
C301  SCD1U16V2KX-3DLGP  [C402H22]  133.1 121.13 90 top
C302  SCD1U16V2KX-3DLGP  [C402H22]  132.03 129.34 180 top
C304  SCD1U16V2KX-3DLGP  [C402H22]  119.38 96.14 90 top
C305  SCD1U16V2KX-3DLGP  [C402H22]  119.38 101.73 90 top
C402  SCD1U16V2KX-L-GP  [C402H22]  128.65 77.53 0 top
C403  SCD1U16V2KX-L-GP  [C402H22]  132.84 74.74 180 top
C601  SCD1U16V2KX-3DLGP  [C402H22]  31.88 122.05 270 top
C602  SCD022U16V2KX-3DLGP  [C402H22]  31.88 122.94 270 top
C603  SCD1U16V2KX-3DLGP  [C402H22]  31.88 121.03 270 top
C801  SC1U10V2KX-1DLGP  [C402H22]  120.14 118.62 90 top
C802  SCD1U25V2KX-1-DL-GP  [C402H22]  129.06 122.68 180 top
C803  SCD1U16V2KX-L-GP  [C402H22]  127.13 119.76 0 top
C804  SC10U25V5KX-DL-GP  [C805H58]  124.21 117.35 180 top
C805  SCD1U16V2KX-3DLGP  [C402H22]  126.24 118.36 270 top
C806  SCD1U16V2KX-L-GP  [C402H22]  122.33 120.78 180 top
C1001  SC22U6D3V3MX-1-DL-GP  [C603H40]  82.85 114.15 90 top
C1002  SC22U6D3V3MX-1-DL-GP  [C603H40]  82.4 116.15 0 top
C1004  SC22U6D3V5MX-L3-GP  [C805H58]  104.78 74.3 90 top
C1005  SC22U6D3V5MX-L3-GP  [C805H58]  73.79 83.19 90 top
C1007  SC22U6D3V5MX-2DLGP  [C805H54]  74.1 108.05 180 top
C1008  SC22U6D3V5MX-2DLGP  [C805H54]  80.58 111.64 180 top
C1009  SC22U6D3V5MX-2DLGP  [C805H54]  80.58 108.08 0 top
C1010  SC22U6D3V5MX-2DLGP  [C805H54]  76.26 108.08 0 top
C1011  SC22U6D3V5MX-2DLGP  [C805H54]  78.42 111.69 0 top
C1012  SC22U6D3V5MX-2DLGP  [C805H54]  76.26 111.64 180 top
C1013  SC22U6D3V5MX-2DLGP  [C805H54]  76.03 115.27 0 top
C1014  SC22U6D3V5MX-2DLGP  [C805H54]  78.19 115.67 180 top
C1015  SC22U6D3V5MX-2DLGP  [C805H54]  80.37 115.67 0 top
C1016  SC22U6D3V5MX-2DLGP  [C805H54]  82.74 111.64 0 top
C1017  SC22U6D3V5MX-2DLGP  [C805H54]  82.74 108.08 180 top
C1018  SC22U6D3V5MX-2DLGP  [C805H54]  78.42 108.08 180 top
C1019  SC22U6D3V5MX-2DLGP  [C805H54]  103.12 76.33 90 top
C1020  SC22U6D3V5MX-2DLGP  [C805H54]  67.69 83.19 270 top
C1021  SC22U6D3V5MX-2DLGP  [C805H54]  83.36 83.08 270 top
C1022  SC22U6D3V5MX-2DLGP  [C805H54]  61.54 83.16 270 top
C1024  SC22U6D3V5MX-L3-GP  [C805H58]  93.22 185.8 90 top
C1025  SC22U6D3V5MX-L3-GP  [C805H58]  78.84 187.6 270 top
C1026  SC22U6D3V5MX-L3-GP  [C805H58]  93.19 187.91 90 top
C1027  SC22U6D3V5MX-L3-GP  [C805H58]  78.79 185.5 270 top
C1028  SC47U6D3V5MX-1DL-GP  [C805H54]  77.62 153.49 0 top
C1029  SC47U6D3V5MX-1DL-GP  [C805H54]  70.92 156.69 0 top
C1030  SC47U6D3V5MX-1DL-GP  [C805H54]  101.9 163.25 0 top
C1031  SC47U6D3V5MX-1DL-GP  [C805H54]  66.93 153.16 0 top
C1032  SC22U6D3V5MX-2DLGP  [C805H54]  122.17 117.35 180 top
C1033  SC1U10V2KX-1DLGP  [C402H22]  120.14 116.33 270 top
C1101  SCD1U16V2KX-3DLGP  [C402H22]  96.29 164.21 0 top
C1102  SCD1U16V2KX-3DLGP  [C402H22]  66.67 160.02 0 top
C1103  SCD1U16V2KX-L-GP  [C402H22]  153.03 184.78 270 top
C1104  SCD1U16V2KX-L-GP  [C402H22]  156.34 184.15 90 top
C1105  SCD1U16V2KX-3DLGP  [C402H22]  13.84 183.9 0 top
C1106  SCD1U16V2KX-3DLGP  [C402H22]  15.68 186.69 270 top
C1107  SC4D7U6D3V3KX-DLGP  [C603H36]  15.49 185.55 270 top
C1108  SCD1U16V2KX-L-GP  [C402H22]  67.34 183.34 270 top
C1109  SCD1U16V2KX-3DLGP  [C402H22]  136.8 186.21 180 top
C1110  SC2D2U6D3V2MX-DL-GP  [C402H22]  145.62 184.76 90 top
C1201  SCD1U16V2KX-L-GP  [C402H22]  95.5 184.98 180 top
C1202  SCD1U16V2KX-3DLGP  [C402H22]  76.56 184.4 180 top
C1203  SC1U10V2KX-1DLGP  [C402H22]  75.67 184.4 180 top
C1204  SC4D7U6D3V3KX-DLGP  [C603H36]  84.15 183.64 270 top
C1205  SCD1U16V2KX-3DLGP  [C402H22]  87.12 183.39 90 top
C1206  SCD1U16V2KX-3DLGP  [C402H22]  156.34 185.04 90 top
C1207  SCD1U16V2KX-3DLGP  [C402H22]  156.34 186.06 90 top
C1208  SCD1U16V2KX-3DLGP  [C402H22]  17.84 185.39 270 top
C1209  SCD022U16V2KX-3DLGP  [C402H22]  22.73 186.82 0 top
C1210  SCD1U16V2KX-3DLGP  [C402H22]  21.97 184.02 90 top
C1211  SC4D7U6D3V3KX-DLGP  [C603H36]  22.35 185.04 90 top
C1212  SCD1U16V2KX-L-GP  [C402H22]  77.6 149.99 180 top
C1213  SCD1U16V2KX-3DLGP  [C402H22]  88.77 160.4 180 top
C1214  SC1U10V2KX-1DLGP  [C402H22]  66.88 156.84 180 top
C1215  SC1U10V2KX-1DLGP  [C402H22]  81.1 163.45 0 top
C1216  SCD1U16V2KX-3DLGP  [C402H22]  137.69 186.21 180 top
C1217  SC2D2U6D3V2MX-DL-GP  [C402H22]  145.62 185.65 90 top
C1701  SCD1U16V2KX-3DLGP  [C402H22]  204.42 160.55 0 top
C1801  SC15P50V2JN-DL-GP  [C402H22]  197.74 128.6 270 top
C1802  SC15P50V2JN-DL-GP  [C402H22]  199.64 128.6 90 top
C1803  SC15P50V2JN-DL-GP  [C402H22]  218.57 164.98 90 top
C1804  SC15P50V2JN-DL-GP  [C402H22]  216.16 164.96 270 top
C2001  SCD1U16V2KX-L-GP  [C402H22]  201.09 119.76 90 top
C2002  SCD1U16V2KX-3DLGP  [C402H22]  221.92 184.76 270 top
C2003  SCD1U16V2KX-3DLGP  [C402H22]  226.97 187.3 270 top
C2004  SC100P50V2JN-3DLGP  [C402H22]  228.07 181.13 90 top
C2005  SCD1U16V2KX-3DLGP  [C402H22]  224.18 184.7 270 top
C2006  SC1U10V2KX-1DLGP  [C402H22]  224.94 173.58 0 top
C2007  SC1U10V2KX-1DLGP  [C402H22]  215.6 174.65 180 top
C2101  SCD1U16V2KX-3DLGP  [C402H22]  217.65 158.37 90 top
C2102  SCD1U16V2KX-3DLGP  [C402H22]  217.12 159.79 0 top
C2103  SC1U10V2KX-1DLGP  [C402H22]  218.01 159.79 0 top
C2104  SCD1U16V2KX-3DLGP  [C402H22]  216.41 148.82 0 top
C2105  SCD1U16V2KX-3DLGP  [C402H22]  217.27 148.82 0 top
C2106  SCD1U16V2KX-3DLGP  [C402H22]  218.14 148.82 0 top
C2107  SCD1U16V2KX-3DLGP  [C402H22]  221.87 160.22 180 top
C2108  SC4D7U6D3V3KX-DLGP  [C603H36]  213.87 126.75 90 top
C2109  SC4D7U6D3V3KX-DLGP  [C603H36]  216.48 132.77 0 top
C2110  SC1U10V2KX-1DLGP  [C402H22]  185.45 158.5 270 top
C2111  SC22U6D3V3MX-1-DL-GP  [C603H40]  185.78 160.27 180 top
C2112  SC22U6D3V3MX-1-DL-GP  [C603H40]  186.99 160.27 180 top
C2113  SCD1U16V2KX-3DLGP  [C402H22]  203.89 126.8 180 top
C2114  SCD1U16V2KX-3DLGP  [C402H22]  215.39 128.91 90 top
C2115  SCD1U16V2KX-3DLGP  [C402H22]  215.39 129.79 90 top
C2116  SCD1U16V2KX-3DLGP  [C402H22]  191.39 123.83 90 top
C2117  SCD1U16V2KX-3DLGP  [C402H22]  224.59 116.33 0 top
C2118  SC22U6D3V3MX-1-DL-GP  [C603H40]  193.42 123.57 180 top
C2119  SC22U6D3V3MX-1-DL-GP  [C603H40]  194.69 123.57 180 top
C2120  SC1U10V2KX-1DLGP  [C402H22]  222.25 125.45 180 top
C2121  SC1U10V2KX-1DLGP  [C402H22]  223.14 125.45 180 top
C2122  SC1U10V2KX-1DLGP  [C402H22]  215.26 115.06 90 top
C2123  SC1U10V2KX-1DLGP  [C402H22]  223.72 116.33 0 top
C2124  SC1U10V2KX-1DLGP  [C402H22]  203.91 124.17 0 top
C2125  SC1U10V2KX-1DLGP  [C402H22]  217.65 157.48 90 top
C2126  SC10U6D3V3MX-DL-GP  [C603H36]  186.82 168.35 0 top
C2127  SC22U6D3V3MX-1-DL-GP  [C603H40]  222.68 116.15 0 top
C2128  SC22U6D3V3MX-1-DL-GP  [C603H40]  221.49 116.15 0 top
C2401  SC100P50V2JN-3DLGP  [C402H22]  107.26 56.29 270 top
C2402  SC2200P50V2KX-2DLGP  [C402H22]  207.09 104.65 180 top
C2403  SC100P50V2JN-3DLGP  [C402H22]  208.03 105.16 180 top
C2404  SC2200P50V2KX-2DLGP  [C402H22]  208.03 103.25 180 top
C2405  SC1U10V2KX-1DLGP  [C402H22]  214.12 93.34 0 top
C2406  SCD1U16V2KX-3DLGP  [C402H22]  213.16 87.68 0 top
C2407  SCD01U50V2KX-1DLGP  [C402H22]  205.36 106.55 180 top
C2408  SCD1U16V2KX-3DLGP  [C402H22]  216.28 97.16 180 top
C2409  SCD1U16V2KX-3DLGP  [C402H22]  213.49 81.53 180 top
C2410  SCD1U16V2KX-3DLGP  [C402H22]  211.51 73.36 90 top
C2411  SC4D7U6D3V3KX-DLGP  [C603H36]  216.66 98.81 90 top
C2412  SC1U10V2KX-1DLGP  [C402H22]  192.15 99.44 270 top
C2413  SC100P50V2JN-3DLGP  [C402H22]  198.35 106.2 90 top
C2414  SC4D7U6D3V3KX-DLGP  [C603H36]  212.22 82.55 0 top
C2415  SCD1U16V2KX-3DLGP  [C402H22]  215.26 93.34 0 top
C2416  SCD1U16V2KX-3DLGP  [C402H22]  205.05 104.62 180 top
C2417  SCD1U16V2KX-3DLGP  [C402H22]  213.23 101.09 180 top
C2418  SCD1U16V2KX-3DLGP  [C402H22]  194.44 103.25 180 top
C2419  SCD1U16V2KX-3DLGP  [C402H22]  191.87 102.46 270 top
C2420  SCD1U16V2KX-3DLGP  [C402H22]  192.2 94.46 270 top
C2421  SCD1U16V2KX-3DLGP  [C402H22]  207.14 80.85 90 top
C2422  SCD1U16V2KX-3DLGP  [C402H22]  198.12 103.12 90 top
C2423  SCD1U16V2KX-3DLGP  [C402H22]  199.14 81.74 0 top
C2424  SC10U6D3V3MX-DL-GP  [C603H36]  192.18 103.53 270 top
C2425  SCD1U16V2KX-3DLGP  [C402H22]  215.9 88.77 90 top
C2426  SCD01U50V2KX-1DLGP  [C402H22]  213.74 90.81 90 top
C2427  SC100P50V2JN-3DLGP  [C402H22]  152.15 115.32 270 top
C2501  SC1U10V2KX-1DLGP  [C402H22]  192.51 207.72 90 top
C2701  SC2D2U10V3KX-1DLGP-U  [C603H36]  62.46 238.3 0 top
C2702  SC2D2U10V3KX-1DLGP-U  [C603H36]  59.66 237.24 270 top
C2703  SC10U25V5KX-DL-GP  [C805H58]  67.06 238 90 top
C2704  SCD1U16V2KX-3DLGP  [C402H22]  69.85 235.84 180 top
C2705  SC10U25V5KX-DL-GP  [C805H58]  74.3 236.47 180 top
C2706  SC10U6D3V3MX-DL-GP  [C603H36]  55.12 235.33 180 top
C2707  SCD1U16V2KX-3DLGP  [C402H22]  56.13 234.95 180 top
C2708  SCD1U16V2KX-3DLGP  [C402H22]  70.74 235.84 180 top
C2709  SC10U25V5KX-DL-GP  [C805H58]  72.26 236.47 180 top
C2710  SC10U25V5KX-DL-GP  [C805H58]  71.63 232.92 90 top
C2711  SC10U25V5KX-DL-GP  [C805H58]  54.1 227.46 270 top
C2712  SCD1U16V2KX-3DLGP  [C402H22]  56.39 227.46 0 top
C2713  SC10U6D3V3MX-DL-GP  [C603H36]  56.39 224.92 0 top
C2714  SCD1U16V2KX-3DLGP  [C402H22]  57.4 224.66 0 top
C2715  SC22P50V2JN-4DLGP  [C402H22]  58.8 225.2 270 top
C2716  SCD1U16V2KX-3DLGP  [C402H22]  70.82 225.81 90 top
C2717  SCD1U16V2KX-3DLGP  [C402H22]  72.21 225.3 0 top
C2718  SCD1U16V2KX-3DLGP  [C402H22]  61.54 224.82 90 top
C2719  SCD1U50V3KX-DL-GP  [C603H35]  20.7 18.29 270 top
C2720  SCD1U50V3KX-DL-GP  [C603H35]  77.98 241.94 270 top
C2721  SCD1U16V2KX-3DLGP  [C402H22]  81.03 234.95 0 top
C2722  SC22U6D3V5MX-2DLGP  [C805H54]  81.13 231.52 90 top
C2901  SC10U25V5KX-DL-GP  [C805H58]  71.63 228.85 90 top
C2902  SC10U25V5KX-L-GP  [C805H56]  71.63 230.89 90 top
C2903  SC100P50V2JN-3DLGP  [C402H22]  72.9 243.46 0 top
C2904  SC4D7U25V5KX-DL-GP  [C805H54]  70.23 242.57 0 top
C2905  SC4D7U25V5KX-DL-GP  [C805H54]  70.23 239.01 180 top
C2906  SC100P50V2JN-3DLGP  [C402H22]  68.2 244.22 90 top
C2907  SC100P50V2JN-3DLGP  [C402H22]  75.44 243.97 90 top
C3001  SC10U25V5KX-DL-GP  [C805H58]  14.69 21.9 270 top
C3002  SC10U25V5KX-DL-GP  [C805H58]  13.49 24.69 0 top
C3003  SC100P50V2JN-3DLGP  [C402H22]  9.03 24.33 90 top
C3004  SC100P50V2JN-3DLGP  [C402H22]  8.95 21.72 90 top
C3005  SC100P50V2JN-3DLGP  [C402H22]  18.41 20.32 90 top
C3006  SC100P50V2JN-3DLGP  [C402H22]  18.35 17.27 90 top
C3007  SC10U25V5KX-DL-GP  [C805H58]  16.38 35.71 0 top
C3008  SC10U25V5KX-DL-GP  [C805H58]  14.35 35.71 0 top
C3009  SC100P50V2JN-3DLGP  [C402H22]  14.48 28.8 270 top
C3010  SC100P50V2JN-3DLGP  [C402H22]  16.51 28.8 90 top
C3101  SCD1U16V2KX-3DLGP  [C402H22]  146.69 39.88 90 top
C3102  SC4D7U6D3V3KX-DLGP  [C603H36]  146.56 38.73 90 top
C3103  SCD1U16V2KX-3DLGP  [C402H22]  142.82 36.8 0 top
C3104  SC4D7U6D3V3KX-DLGP  [C603H36]  136.25 46.69 270 top
C3105  SCD1U16V2KX-3DLGP  [C402H22]  134.37 36.58 270 top
C3106  SCD1U16V2KX-3DLGP  [C402H22]  134.11 39.12 0 top
C3107  SCD1U16V2KX-3DLGP  [C402H22]  139.65 36.7 0 top
C3108  SCD1U16V2KX-3DLGP  [C402H22]  141.07 48.36 90 top
C3109  SCD1U16V2KX-3DLGP  [C402H22]  147.66 45.56 90 top
C3110  SCD1U16V2KX-3DLGP  [C402H22]  147.66 44.66 90 top
C3111  SCD1U16V2KX-3DLGP  [C402H22]  141.07 47.47 90 top
C3112  SC1U10V2KX-1DLGP  [C402H22]  136.3 45.59 270 top
C3113  SCD1U16V2KX-3DLGP  [C402H22]  136.27 49.34 0 top
C3114  SC4D7U6D3V3KX-DLGP  [C603H36]  134.42 35.47 270 top
C3115  SCD1U16V2KX-3DLGP  [C402H22]  148.79 43.14 90 top
C3116  SCD1U16V2KX-3DLGP  [C402H22]  148.79 42.25 90 top
C3117  SC10U6D3V3MX-DL-GP  [C603H36]  135.13 49.4 0 top
C3118  SC20P50V2JN-1-DL-GP  [C402H22]  133.88 41.38 0 top
C3119  SC20P50V2JN-1-DL-GP  [C402H22]  133.91 44.68 180 top
C3201  SC1U10V2KX-1DLGP  [C402H22]  110.62 18.16 270 top
C3301  SCD1U16V2KX-3DLGP  [C402H22]  42.29 228.6 90 top
C3302  SC4D7U6D3V3KX-DLGP  [C603H36]  42.67 227.46 90 top
C3303  SC1U10V2KX-1DLGP  [C402H22]  36.96 228.09 0 top
C3304  SC1U10V2KX-1DLGP  [C402H22]  45.85 230.76 90 top
C3305  SC6D8P50V2CN-DL-GP  [C402H22]  41.78 237.62 0 top
C3306  SC10U6D3V3MX-DL-GP  [C603H36]  45.21 237.62 270 top
C3307  SCD1U16V2KX-3DLGP  [C402H22]  45.21 238.63 270 top
C3801  SCD1U16V2KX-3DLGP  [C402H22]  95.89 230.89 180 top
C3802  SCD1U16V2KX-3DLGP  [C402H22]  95 230.89 180 top
C3803  SCD1U16V2KX-3DLGP  [C402H22]  106.17 230.99 180 top
C3804  SCD1U16V2KX-3DLGP  [C402H22]  105.28 230.99 180 top
C3805  SC1U10V2KX-1DLGP  [C402H22]  86.23 227.58 270 top
C3806  SCD1U16V2KX-3DLGP  [C402H22]  107.95 239.45 270 top
C3807  SCD1U16V2KX-3DLGP  [C402H22]  114.3 235.33 270 top
C3901  SC1U10V2KX-1DLGP  [C402H22]  92.58 16.26 0 top
C4001  SCD1U16V2KX-3DLGP  [C402H22]  188.14 177.06 270 top
C4002  SCD1U16V2KX-3DLGP  [C402H22]  155.52 33.12 0 top
C4003  SCD1U16V2KX-3DLGP  [C402H22]  95.25 23.37 0 top
C4004  SCD1U16V2KX-3DLGP  [C402H22]  155.19 26.16 0 top
C4005  SCD1U16V2KX-3DLGP  [C402H22]  155.07 19.18 0 top
C4006  SCD1U16V2KX-3DLGP  [C402H22]  91.34 26.87 180 top
C4007  SCD1U16V2KX-3DLGP  [C402H22]  76.56 22.23 270 top
C4008  SCD1U16V2KX-3DLGP  [C402H22]  76.56 23.27 270 top
C4009  SC1U10V2KX-1DLGP  [C402H22]  153.29 204.98 270 top
C4010  SCD1U16V2KX-3DLGP  [C402H22]  150.5 198.5 180 top
C4011  SCD1U16V2KX-3DLGP  [C402H22]  145.29 197.1 0 top
C4012  SC1U10V2KX-1DLGP  [C402H22]  144.78 195.71 90 top
C4013  SC1U10V2KX-1DLGP  [C402H22]  46.23 186.69 180 top
C4201  SC1KP50V2KX-1DLGP  [C402H22]  95.76 215.9 90 top
C4202  SC1KP50V2KX-1DLGP  [C402H22]  95.76 214.88 90 top
C4203  SC1U10V2KX-1DLGP  [C402H22]  90.27 218.31 90 top
C4204  SC1U10V2KX-1DLGP  [C402H22]  91.01 212.65 90 top
C4205  SC10U6D3V3MX-DL-GP  [C603H36]  93.85 211.66 0 top
C4206  SC10U6D3V3MX-DL-GP  [C603H36]  92.58 211.66 0 top
C4207  SC10U25V5KX-L-GP  [C805H56]  92.79 222.07 270 top
C4208  SC10U25V5KX-DL-GP  [C805H58]  92.79 220.04 270 top
C4209  SCD1U25V2KX-1-DL-GP  [C402H22]  92.74 209.85 270 top
C4210  SCD1U25V2KX-1-DL-GP  [C402H22]  94.23 207.9 0 top
C4211  SC10U25V5KX-L-GP  [C805H56]  91.57 201.8 270 top
C4212  SCD1U16V2KX-3DLGP  [C402H22]  96.27 207.9 180 top
C4213  SCD1U16V2KX-3DLGP  [C402H22]  196.85 217.04 180 top
C4214  SCD01U50V2KX-L-GP  [C402H22]  195.83 216.15 0 top
C4215  SCD1U16V2KX-L-GP  [C402H22]  175.77 219.58 0 top
C4216  SCD1U16V2KX-3DLGP  [C402H22]  172.85 220.85 180 top
C4217  SC1U50V3KX-1-GP  [C603H36]  176.83 217.81 180 top
C4303  SC1U50V3KX-1-GP  [C603H36]  32.51 46.35 90 top
C4305  SCD1U16V2KX-3DLGP  [C402H22]  219.2 218.57 0 top
C4306  SCD1U16V2KX-3DLGP  [C402H22]  220.34 217.17 270 top
C4307  SCD1U16V2KX-3DLGP  [C402H22]  222.63 228.85 180 top
C4308  SCD1U16V2KX-L-GP  [C402H22]  208.99 218.49 0 top
C4309  SCD1U16V2KX-3DLGP  [C402H22]  209.88 218.49 0 top
C4310  SCD1U16V2KX-L-GP  [C402H22]  195.45 227.71 180 top
C4311  SCD1U16V2KX-3DLGP  [C402H22]  196.34 227.71 180 top
C5101  SCD1U16V2KX-3DLGP  [C402H22]  232.24 156.64 180 top
C5301  SC470P50V2KX-3DLGP  [C402H22]  183.01 13.16 180 top
C5302  SCD1U16V2KX-3DLGP  [C402H22]  178.31 13.08 180 top
C5303  SC10U25V5KX-DL-GP  [C805H58]  174.5 11.68 270 top
C5304  SC10U25V5KX-DL-GP  [C805H58]  184.78 14.73 180 top
C5601  SCD1U16V2KX-3DLGP  [C402H22]  37.79 20.01 270 top
C5602  SCD1U16V2KX-3DLGP  [C402H22]  37.79 20.9 270 top
C5603  SCD1U16V2KX-3DLGP  [C402H22]  34.29 23.47 0 top
C5604  SCD1U16V2KX-3DLGP  [C402H22]  33.4 23.47 0 top
C5605  SCD1U16V2KX-3DLGP  [C402H22]  31.47 24.56 0 top
C5606  SCD1U16V2KX-3DLGP  [C402H22]  30.59 24.56 0 top
C5607  SCD1U16V2KX-3DLGP  [C402H22]  28.68 23.54 0 top
C5608  SCD1U16V2KX-3DLGP  [C402H22]  27.76 23.55 0 top
C5609  SCD1U25V2KX-1-DL-GP  [C402H22]  21.46 14.22 270 top
C5610  SC470P50V2KX-3DLGP  [C402H22]  24.89 18.29 90 top
C5611  SC470P50V2KX-3DLGP  [C402H22]  22.99 18.29 270 top
C5612  SCD1U16V2KX-3DLGP  [C402H22]  42.16 9.78 0 top
C5613  SCD1U16V2KX-3DLGP  [C402H22]  38.99 8.51 270 top
C5901  SC2D2U10V3KX-1DLGP-U  [C603H36]  67.49 18.95 0 top
C5902  SCD1U16V2KX-3DLGP  [C402H22]  66.45 19.33 0 top
C5903  SCD1U16V2KX-3DLGP  [C402H22]  63.27 27.69 0 top
C5904  SCD1U16V2KX-3DLGP  [C402H22]  56.01 23.37 180 top
C5905  SCD1U16V2KX-3DLGP  [C402H22]  68.55 21.44 90 top
C5906  SCD1U16V2KX-3DLGP  [C402H22]  54.48 18.8 0 top
C5907  SC4D7U6D3V3KX-DLGP  [C603H36]  53.34 18.41 0 top
C5908  SCD1U16V2KX-3DLGP  [C402H22]  66.34 26.9 180 top
C5909  SCD1U16V2KX-3DLGP  [C402H22]  56.64 17.27 0 top
C5910  SCD1U16V2KX-3DLGP  [C402H22]  65.12 27.72 180 top
C5911  SCD1U16V2KX-3DLGP  [C402H22]  64.23 27.72 180 top
C5912  SCD1U16V2KX-3DLGP  [C402H22]  62.29 28.61 180 top
C5913  SCD1U16V2KX-3DLGP  [C402H22]  61.4 28.61 180 top
C5914  SCD1U16V2KX-3DLGP  [C402H22]  59.96 28.86 180 top
C5915  SCD1U16V2KX-3DLGP  [C402H22]  59.02 28.86 180 top
C5916  SC22P50V2JN-4DLGP  [C402H22]  61.16 17.31 270 top
C5917  SC22P50V2JN-4DLGP  [C402H22]  63.1 17.28 270 top
C5918  SC22P50V2JN-4DLGP  [C402H22]  65.06 17.3 90 top
C5919  SC22P50V2JN-4DLGP  [C402H22]  59.79 13.69 270 top
C5920  SC22P50V2JN-4DLGP  [C402H22]  62.1 13.72 90 top
C5921  SC22P50V2JN-4DLGP  [C402H22]  64.85 13.49 90 top
C5922  SC2P50V2CN-3-GP  [C402H22]  56.52 15.24 180 top
C5923  SC2P50V2CN-3-GP  [C402H22]  59.03 16.51 90 top
C6001  SCD01U50V2KX-1DLGP  [C402H22]  137.54 193.17 270 top
C6002  SCD01U50V2KX-1DLGP  [C402H22]  137.54 192.28 270 top
C6003  SCD01U50V2KX-1DLGP  [C402H22]  134.75 195.58 270 top
C6004  SCD01U50V2KX-1DLGP  [C402H22]  134.75 194.69 270 top
C6005  SCD01U50V2KX-1DLGP  [C402H22]  107.95 195.2 180 top
C6006  SCD01U50V2KX-1DLGP  [C402H22]  107.06 195.2 180 top
C6007  SCD01U50V2KX-1DLGP  [C402H22]  103.25 195.2 180 top
C6008  SCD01U50V2KX-1DLGP  [C402H22]  104.14 195.2 180 top
C6009  SCD01U50V2KX-1DLGP  [C402H22]  115.95 191.13 270 top
C6010  SCD01U50V2KX-1DLGP  [C402H22]  115.95 192.02 270 top
C6011  SCD01U50V2KX-1DLGP  [C402H22]  111.38 195.2 0 top
C6012  SCD01U50V2KX-1DLGP  [C402H22]  112.27 195.2 0 top
C6013  SCD01U50V2KX-1DLGP  [C402H22]  129.92 195.2 180 top
C6014  SCD01U50V2KX-1DLGP  [C402H22]  128.91 195.2 180 top
C6015  SCD01U50V2KX-1DLGP  [C402H22]  125.09 195.2 180 top
C6016  SCD01U50V2KX-1DLGP  [C402H22]  125.98 195.2 180 top
C6017  SC10U25V5KX-DL-GP  [C805H58]  136.91 226.95 270 top
C6018  SC10U25V5KX-DL-GP  [C805H58]  174.88 227.84 270 top
C6019  SC10U25V5KX-DL-GP  [C805H58]  174.88 223.9 270 top
C6020  SC10U25V5KX-DL-GP  [C805H58]  136.91 223.9 270 top
C6201  SC1U10V2KX-1DLGP  [C402H22]  154.97 139.06 90 top
C6202  SCD22U10V2KX-2-GP  [C402H22]  137.87 141.5 0 top
C6203  SCD1U16V2KX-3DLGP  [C402H22]  154.97 140.08 90 top
C6204  SCD22U10V2KX-2-GP  [C402H22]  138.89 141.5 0 top
C6205  SCD1U16V2KX-3DLGP  [C402H22]  134.87 137.85 270 top
C6206  SC10U25V5KX-DL-GP  [C805H58]  135.08 140.21 270 top
C6207  SCD22U10V2KX-2-GP  [C402H22]  140.89 141.48 0 top
C6208  SCD22U10V2KX-2-GP  [C402H22]  141.86 141.48 0 top
C6209  SCD22U10V2KX-2-GP  [C402H22]  143.87 141.48 0 top
C6210  SCD22U10V2KX-2-GP  [C402H22]  144.88 141.48 0 top
C6211  SCD22U10V2KX-2-GP  [C402H22]  149.12 141.99 0 top
C6212  SCD22U10V2KX-2-GP  [C402H22]  150.06 141.99 0 top
C6213  SCD1U16V2KX-3DLGP  [C402H22]  134.87 138.73 270 top
C6214  SC10U25V5KX-DL-GP  [C805H58]  154.38 143.64 270 top
C6301  SCD1U16V2KX-3DLGP  [C402H22]  212.8 206.48 90 top
C6302  SCD1U16V2KX-3DLGP  [C402H22]  212.8 205.59 90 top
C6303  SCD1U16V2KX-3DLGP  [C402H22]  212.06 187.93 90 top
C6304  SCD1U16V2KX-3DLGP  [C402H22]  212.06 188.82 90 top
C6305  SCD1U16V2KX-3DLGP  [C402H22]  197.23 196.85 270 top
C6306  SCD1U16V2KX-3DLGP  [C402H22]  197.23 195.96 270 top
C6307  SC10U6D3V3MX-DL-GP  [C603H36]  213.03 210.92 90 top
C6308  SC22U6D3V3MX-1-DL-GP  [C603H40]  213.03 209.65 90 top
C6309  SCD1U16V2KX-3DLGP  [C402H22]  212.8 207.37 90 top
C6310  SCD1U16V2KX-3DLGP  [C402H22]  203.1 209.78 270 top
C6401  SC1U10V2KX-1DLGP  [C402H22]  23.34 234.87 90 top
C6402  SCD1U16V2KX-3DLGP  [C402H22]  20.85 234.37 0 top
C6403  SCD1U16V2KX-3DLGP  [C402H22]  11.94 234.34 0 top
C9101  SC10U6D3V3MX-DL-GP  [C603H36]  200.15 180.72 0 top
C9102  SCD1U16V2KX-3DLGP  [C402H22]  201.42 180.34 0 top
C9103  SCD1U16V2KX-3DLGP  [C402H22]  206.88 172.59 0 top
C9104  SC10U6D3V3MX-DL-GP  [C603H36]  211.2 181.48 0 top
C9105  SCD1U16V2KX-3DLGP  [C402H22]  210.06 181.61 0 top
C9106  SCD1U16V2KX-3DLGP  [C402H22]  177.29 208.41 90 top
C9201  SCD1U16V2KX-3DLGP  [C402H22]  229.72 17.96 180 top
C9202  SCD1U16V2KX-3DLGP  [C402H22]  212.34 9.65 0 top
C9203  SCD1U16V2KX-3DLGP  [C402H22]  216.53 32.77 0 top
C9204  SCD1U16V2KX-3DLGP  [C402H22]  230.38 25.4 0 top
C9205  SCD1U16V2KX-3DLGP  [C402H22]  229.62 40.64 180 top
C9206  SCD1U16V2KX-3DLGP  [C402H22]  229.74 94.36 180 top
C9207  SCD1U16V2KX-3DLGP  [C402H22]  230.38 82.17 0 top
C9208  SCD1U16V2KX-3DLGP  [C402H22]  230.5 59.05 0 top
C9209  SCD1U16V2KX-3DLGP  [C402H22]  230.25 45.47 0 top
C9301  SCD22U10V2KX-2-GP  [C402H22]  176.93 36.55 90 top
C9302  SCD22U10V2KX-2-GP  [C402H22]  176.99 39.73 90 top
C9303  SCD22U10V2KX-2-GP  [C402H22]  177.02 43.67 90 top
C9304  SCD22U10V2KX-2-GP  [C402H22]  176.93 35.66 90 top
C9305  SCD22U10V2KX-2-GP  [C402H22]  176.99 40.62 90 top
C9306  SCD22U10V2KX-2-GP  [C402H22]  177.02 44.56 90 top
C9307  SCD22U10V2KX-2-GP  [C402H22]  176.94 48.62 90 top
C9308  SCD22U10V2KX-2-GP  [C402H22]  176.94 47.73 90 top
C9309  SCD22U10V2KX-2-GP  [C402H22]  176.95 54.44 90 top
C9310  SCD1U16V2KX-3DLGP  [C402H22]  190.25 23.24 180 top
C9311  SCD1U16V2KX-3DLGP  [C402H22]  188.9 28.18 180 top
C9312  SCD1U16V2KX-3DLGP  [C402H22]  209.68 29.21 0 top
C9313  SCD22U10V2KX-2-GP  [C402H22]  176.95 53.55 90 top
C9314  SCD22U10V2KX-2-GP  [C402H22]  176.94 58.56 90 top
C9315  SCD22U10V2KX-2-GP  [C402H22]  176.94 57.66 90 top
C9316  SCD22U10V2KX-2-GP  [C402H22]  176.94 62.62 90 top
C9317  SCD22U10V2KX-2-GP  [C402H22]  176.94 61.73 90 top
C9318  SCD22U10V2KX-2-GP  [C402H22]  176.97 66.58 90 top
C9319  SCD22U10V2KX-2-GP  [C402H22]  176.97 65.69 90 top
C9320  SCD22U10V2KX-2-GP  [C402H22]  176.95 72.62 90 top
C9321  SCD22U10V2KX-2-GP  [C402H22]  176.95 71.73 90 top
C9322  SCD22U10V2KX-2-GP  [C402H22]  176.97 76.61 90 top
C9323  SCD22U10V2KX-2-GP  [C402H22]  176.97 75.72 90 top
C9324  SCD22U10V2KX-2-GP  [C402H22]  176.99 80.6 90 top
C9325  SCD22U10V2KX-2-GP  [C402H22]  176.99 79.71 90 top
C9326  SCD22U10V2KX-2-GP  [C402H22]  176.99 84.61 90 top
C9328  SCD22U10V2KX-2-GP  [C402H22]  176.99 83.72 90 top
C9329  SCD22U10V2KX-2-GP  [C402H22]  176.95 88.6 90 top
C9331  SCD22U10V2KX-2-GP  [C402H22]  176.95 87.71 90 top
C9332  SCD22U10V2KX-2-GP  [C402H22]  176.99 92.59 90 top
C9334  SCD22U10V2KX-2-GP  [C402H22]  176.99 91.7 90 top
C9335  SCD22U10V2KX-2-GP  [C402H22]  176.97 95.66 90 top
C9336  SCD22U10V2KX-2-GP  [C402H22]  176.97 96.55 90 top
C9337  SCD22U10V2KX-2-GP  [C402H22]  176.98 99.77 90 top
C9338  SCD22U10V2KX-2-GP  [C402H22]  176.98 100.66 90 top
C9401  SCD22U10V2KX-2-GP  [C402H22]  168.78 35.69 270 top
C9402  SCD22U10V2KX-2-GP  [C402H22]  168.78 36.58 270 top
C9403  SCD1U16V2KX-3DLGP  [C402H22]  168.99 26.4 0 top
C9404  SCD1U16V2KX-3DLGP  [C402H22]  169.93 29.34 180 top
C9405  SCD1U16V2KX-3DLGP  [C402H22]  170.71 24.08 180 top
C9406  SCD22U10V2KX-2-GP  [C402H22]  197.36 33.93 90 top
C9407  SCD22U10V2KX-2-GP  [C402H22]  197.36 34.82 90 top
C9408  SCD1U16V2KX-3DLGP  [C402H22]  209.68 26.81 0 top
C9409  SCD1U16V2KX-3DLGP  [C402H22]  209.68 22.4 180 top
C9410  SCD1U16V2KX-3DLGP  [C402H22]  188.98 30.23 0 top
C9411  SC10U6D3V3MX-DL-GP  [C603H36]  212.06 35.79 180 top
C9501  SCD1U16V2KX-3DLGP  [C402H22]  191.8 54.94 270 top
C9502  SCD1U16V2KX-3DLGP  [C402H22]  191.8 55.83 270 top
C9503  SCD1U16V2KX-3DLGP  [C402H22]  193.32 51.89 270 top
C9504  SCD1U16V2KX-3DLGP  [C402H22]  193.32 51 270 top
C9505  SCD01U50V2KX-1DLGP  [C402H22]  209.85 45.39 90 top
C9506  SCD1U16V2KX-3DLGP  [C402H22]  209.85 44.5 90 top
C9507  SC1U10V2KX-1DLGP  [C402H22]  209.85 46.28 90 top
C9508  SC10U6D3V3MX-DL-GP  [C603H36]  209.6 43.46 90 top
C9509  SCD01U50V2KX-1DLGP  [C402H22]  194.49 65.28 90 top
C9510  SCD1U16V2KX-3DLGP  [C402H22]  194.49 66.29 90 top
C9511  SC1U10V2KX-1DLGP  [C402H22]  194.49 67.31 90 top
C9512  SC10U6D3V3MX-DL-GP  [C603H36]  194.36 68.45 90 top
C9513  SCD1U16V2KX-3DLGP  [C402H22]  202.01 46.61 90 top
C9514  SC1U10V2KX-1DLGP  [C402H22]  200.46 66.42 90 top
C9515  SC1U10V2KX-1DLGP  [C402H22]  215.24 55.5 90 top
C9516  SCD1U16V2KX-3DLGP  [C402H22]  193.47 58.52 180 top
C9517  SC1U10V2KX-1DLGP  [C402H22]  191.67 58.52 180 top
C9518  SC1U10V2KX-1DLGP  [C402H22]  192.58 58.52 180 top
C9519  SCD1U16V2KX-3DLGP  [C402H22]  199.36 46.61 90 top
C9520  SC1U10V2KX-1DLGP  [C402H22]  204.47 46.58 90 top
C9521  SC10U6D3V3MX-DL-GP  [C603H36]  214.55 64.03 180 top
C9522  SCD1U16V2KX-3DLGP  [C402H22]  192.35 64.72 270 top
C9523  SCD1U16V2KX-3DLGP  [C402H22]  193.73 53.54 0 top
C9524  SC10U6D3V3MX-DL-GP  [C603H36]  191.97 65.76 270 top
C9525  SC10U6D3V3MX-DL-GP  [C603H36]  191.74 53.14 0 top
C9526  SC1U10V2KX-1DLGP  [C402H22]  192.35 63.83 270 top
C9527  SC1U10V2KX-1DLGP  [C402H22]  192.84 53.54 0 top
C9901  SCD1U16V2KX-3DLGP  [C402H22]  132.14 62.48 90 bottom
CPU1  SKYLAKE-1,SKL-S,LAKE-S,CFL-S  [SKTBGA1151R754612-UH369]  78.3 111.88 180 top
D2501  RB551V30-GP  [SOD323AKH38]  135.13 217.42 90 top
D2502  BAT54C-12-GP  [SOT-23-9H44]  132.17 220.49 0 top
D2601  RB551V30-GP  [SOD323AKH38]  15.62 130.18 90 top
D2602  RB551V30-GP  [SOD323AKH38]  80.52 11.81 180 top
D2701  AZ5125-01H-R7G-GP  [SOD-523-4H28]  76.2 233.68 90 top
D2901  LBAT54ALT1G-1-GP  [SOT23-2D4-123H44]  64.64 241.17 90 top
D4201  SM240AF-GP  [D4626-D914AKH44]  196.98 222.63 0 top
D4303  BAT54C-12-GP  [SOT-23-9H44]  212.45 217.53 0 top
D5301  SSM14-1-GP  [D5126145AKH91]  190.12 10.29 90 top
D5601  RB551V30-GP  [SOD323AKH38]  44.7 9.78 90 top
D6301  RB551V30-GP  [SOD323AKH38]  200.94 212.52 0 top
D6302  RB551V30-GP  [SOD323AKH38]  203 212.55 0 top
DB2001  0R3J-0-U-GP  [R603H22]  212.67 168.5 180 top
DIMM1  DDR4-288P-82-GP  [AH08847-A9L2-4M]  88.96 169.83 0 top
DIMM2  DDR4-288P-82-GP  [AH08847-A9L2-4M]  88.96 178.81 0 top
EU3201  AZC199-04SDR7G-1-GP  [SOT-6-1H58]  138.56 28.96 0 top
EU3202  AZC199-04SDR7G-1-GP  [SOT-6-1H58]  130.63 29.18 180 top
EU3203  AZC199-04SDR7G-1-GP  [SOT-6-1H58]  143.1 28.93 0 top
EU3204  AZC199-04SDR7G-1-GP  [SOT-6-1H58]  147.78 28.78 0 top
EU3801  AZ1045-04F-R7G-GP  [DFN10G2510H26]  94.23 238.63 180 top
EU3802  AZ1045-04F-R7G-GP  [DFN10G2510H26]  104.65 238.73 180 top
EU3803  AZC199-04SDR7G-1-GP  [SOT-6-1H58]  99.26 238.94 0 top
EU3901  AZC199-04SDR7G-1-GP  [SOT-6-1H58]  106.55 19.94 0 top
EU5601  AZ1045-04F-R7G-GP  [DFN10G2510H26]  31.75 13.59 0 top
EU5602  AZ1045-04F-R7G-GP  [DFN10G2510H26]  28.19 13.59 0 top
EU5603  AZ1045-04F-R7G-GP  [DFN10G2510H26]  24.26 13.59 0 top
EU5901  TVLST2304BD0-1-GP  [SOT-6H58]  61.11 11.25 90 top
EU5902  TVLST2304BD0-1-GP  [SOT-6H58]  53.72 11.33 90 top
F3301  POLYSW-1D1A6V-9-GP-U  [POLYSW-2114H30]  45.62 235.89 90 top
F5901  POLYSW-1D1A6V-9-GP-U  [POLYSW-2114H30]  45.09 15.62 270 top
FANC1  BAOT-CON4-S5-GP  [P254-1104A0ADKP-W]  10.16 129.41 90 top
FANS1  FOX-CON4-S19-GP  [HF2704F-RM1]  85.09 5.71 0 top
FL2901  MCB1005S121FBP-GP  [L402H24]  73.91 243.46 180 top
FL2902  MCB1005S121FBP-GP  [L402H24]  74.93 242.57 180 top
FL2903  MCB1005S121FBP-GP  [L402H24]  67.69 242.82 180 top
HDMI1  SKT-HDMI23-47-GP-U  [SKT-HDMI23-150122-9-U]  27.95 9.36 0 top
HPMIC1  AUDIO-JK631-GP  [2SJ3062-004111F]  70.5 256 180 top
HS1901  FOX-CON2-3-GP  [HB9603E-DW]  183.4 167.9 270 top
HS1902  FOX-CON2-3-GP  [HB9603E-DW]  220 122.1 90 top
HS2601  GEN315R158-8-F-C-S-GP-U  [GEN315R158-8-F-C-S-U]  6.35 33.02 0 top
HS2602  GEN315R158-8-F-C-S-GP-U  [GEN315R158-8-F-C-S-U]  9.65 160.02 0 top
HS2603  GEN315R158-8-F-C-S-GP-U  [GEN315R158-8-F-C-S-U]  9.65 223.94 0 top
HS2604  GEN315R158-8-F-C-S-GP-U  [GEN315R158-8-F-C-S-U]  163.83 10.16 0 top
HS2605  GEN315R158-8-F-C-S-GP-U  [GEN315R158-8-F-C-S-U]  157.65 160.02 0 top
HS2606  GEN315R158-8-F-C-S-GP-U  [GEN315R158-8-F-C-S-U]  163.83 228.49 0 top
HS2607  GEN315R158-8-F-C-S-GP-U  [GEN315R158-8-F-C-S-U]  235.35 10.16 0 top
HS2608  GEN315R158-8-F-C-S-GP-U  [GEN315R158-8-F-C-S-U]  229.87 165.1 0 top
HS6301  STF256R109H99-GP  [STF256R109H99]  235.25 197 0 top
JMP1  PIN-CONN6A-S3-GP  [21S-92-03GB16]  230.2 176.28 0 top
L2101  HCB1608KF-601T10-GP  [L603H38]  186.99 157.56 180 top
